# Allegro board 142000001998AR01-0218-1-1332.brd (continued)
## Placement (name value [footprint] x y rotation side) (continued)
R20  49.9  [RC0402]  90.95 114.25 90 top
R21  10K  [RC0402]  94.43 113.95 180 top
R22  @0  [RC0402]  69.56 113.52 90 top
R23  10K  [RC0402]  64.99 113.48 90 top
R24  10K  [RC0402]  77.82 113.39 270 top
R25  33  [RC0402]  86.72 113.31 90 top
R26  0  [RC0402]  90.95 113.28 90 top
R27  0  [RC0402]  73.56 112.88 90 top
R28  4.7K  [RC0402]  82.88 112.81 270 top
R29  @49.9  [RC0402]  69.57 112.6 270 top
R30  4.7K  [RC0402]  65 112.55 90 top
R31  0  [RC0402]  77.83 112.44 270 top
R32  0  [RC0402]  73.55 111.96 90 top
R33  10K  [RC0402]  60.2 111.82 90 top
R34  @10K  [RC0402]  131.17 112.17 90 top
R35  @0  [RC0402]  69.56 111.65 90 top
R36  @10K  [RC0402]  170.56 119.13 0 top
R37  0  [RC0402]  86.69 111.4 270 top
R38  @0  [RC0402]  81.46 110.97 0 top
R39  10K  [RC0402]  65 110.97 270 top
R40  0  [RC0402]  77.88 110.74 270 top
R41  33  [RC0402]  90.98 110.69 90 top
R42  3K  [RC0402]  132.18 111.05 270 top
R43  @4.7K  [RC0402]  82.88 110.54 270 top
R44  0  [RC0402]  73.58 110.49 90 top
R45  0  [RC0402]  86.69 110.44 270 top
R46  2K  [RC0402]  130.78 110.61 0 top
R47  0  [RC0402]  65 110.03 90 top
R48  0  [RC0402]  101.06 109.99 0 top
R49  @0  [RC0402]  100.08 109.99 0 top
R50  10K  [RC0402]  98.18 109.99 180 top
R51  49.9  [RC0402]  102.03 109.98 180 top
R52  33  [RC0402]  99.11 109.98 180 top
R53  10K  [RC0402]  97.2 109.96 0 top
R54  49.9  [RC0402]  96.24 109.96 180 top
R55  10K  [RC0402]  22.07 109.86 0 top
R56  @10K  [RC0402]  23.14 109.86 0 top
R57  4.7K  [RC0402]  77.87 109.81 270 top
R58  51  [RC0402]  20.98 109.8 0 top
R59  51  [RC0402]  17.75 109.78 0 top
R60  51  [RC0402]  19.46 109.78 0 top
R61  49.9  [RC0402]  69.54 109.78 270 top
R62  @10K  [RC0402]  169.54 119.13 180 top
R63  @4.7K  [RC0402]  86.66 109.5 90 top
R64  @10K  [RC0402]  94.08 109.37 270 top
R65  0  [RC0402]  90.5 109.25 0 top
R66  0  [RC0402]  64.99 109.07 90 top
R67  0  [RC0402]  77.88 108.84 90 top
R68  22.1K  [RC0402]  132.23 108.76 90 top
R69  0  [RC0402]  69.54 108.23 270 top
R70  33  [RC0402]  64.85 108.51 270 bottom
R71  1K  [RC0402]  93.59 108.05 0 top
R72  0  [RC0402]  94.59 108.05 180 top
R73  0  [RC0402]  73.73 108.05 270 top
R74  121K  [RC0402]  132.23 107.87 270 top
R75  0  [RC0402]  73.73 107.14 270 top
R77  0  [RC0402]  132.23 106.86 90 top
R78  33  [RC0402]  163.07 118.62 180 top
R79  0  [RC0402]  83.01 106.4 0 top
R80  0  [RC0402]  83.97 106.4 0 top
R82  0  [RC0402]  85.55 106.35 0 top
R83  0  [RC0402]  86.51 106.35 0 top
R84  10K  [RC0402]  78.69 106.02 180 top
R85  4.7K  [RC0402]  79.55 106.02 180 top
R86  0  [RC0402]  77.78 106.01 0 top
R87  0  [RC0402]  132.23 105.97 270 top
R88  0  [RC0402]  81.58 105.92 270 top
R89  @1K  [RC0402]  94.67 105.38 270 top
R90  4.7K  [RC0402]  89.64 105.52 180 top
R91  4.7K  [RC0402]  75.01 105.15 180 top
R92  0  [RC0402]  131.27 104.95 90 top
R93  0  [RC0402]  3.72 104.74 270 top
R94  10K  [RC0402]  71.15 104.57 180 top
R95  4.7K  [RC0402]  179.02 92.67 180 top
R96  @4.7K/DNI  [RC0402]  179.9 92.67 0 top
R97  4.7K  [RC0402]  180.92 92.67 0 top
R98  0  [RC0402]  72.54 104.17 180 top
R99  0/0603  [RC0603]  132.63 102.5 270 top
R100  10M  [RC0603]  95.5 103.76 90 top
R101  0  [RC0402]  74.55 103.73 90 top
R102  0  [RC0402]  85.45 103.73 0 top
R103  0  [RC0402]  86.41 103.73 0 top
R104  0  [RC0402]  87.5 103.73 0 top
R105  0  [RC0402]  79.55 103.68 180 top
R106  0  [RC0402]  83.87 103.68 180 top
R107  0  [RC0402]  77.65 103.59 0 top
R108  4.7K  [RC0402]  92.41 103.59 180 top
R109  4.7K  [RC0402]  93.32 103.59 180 top
R110  0  [RC0402]  91.49 103.58 180 top
R111  0  [RC0402]  88.65 103.55 0 top
R112  0  [RC0402]  89.64 103.55 0 top
R113  1K  [RC0603]  3.72 103.37 270 top
R114  @0  [RC0402]  82.3 103.22 0 top
R115  @0  [RC0402]  81.03 103.2 0 top
R116  0  [RC0402]  76.63 102.19 180 top
R117  20K  [RC0402]  99.26 102.08 180 top
R118  0  [RC0402]  100.23 102.08 0 top
R119  33  [RC0402]  160.02 114.17 0 bottom
R120  33  [RC0402]  159 114.17 0 bottom
R121  0  [RC0402]  88.55 100.55 0 top
R122  33  [RC0402]  103.99 100.39 0 top
R123  33  [RC0402]  104.98 100.39 0 top
R124  0  [RC0402]  90.17 100.22 0 top
R125  0  [RC0402]  91.57 100.18 0 top
R126  0  [RC0402]  92.91 100.13 0 top
R127  18K  [RC0603]  100.2 99.4 90 top
R128  33  [RC0402]  113.57 98.07 0 top
R129  33  [RC0402]  109.52 98.01 0 top
R130  33  [RC0402]  110.79 98.01 0 top
R131  0  [RC0402]  88.39 92.58 180 bottom
R132  0  [RC0402]  199.19 98.52 90 bottom
R133  0  [RC0402]  199.15 97.13 0 bottom
R134  0  [RC0402]  202.79 92.26 270 top
R135  0  [RC0402]  199.36 95.71 270 bottom
R136  33  [RC0402]  99.54 96.53 0 top
R137  0  [RC0402]  100.48 96.53 0 top
R138  0  [RC0402]  101.42 96.53 0 top
R139  0  [RC0402]  102.36 96.53 0 top
R140  1M  [RC0402]  98.61 96.52 180 top
R141  150  [RC0402]  105.61 95.56 0 top
R142  10K  [RC0402]  103.5 95.54 180 top
R143  10K  [RC0402]  104.47 95.54 180 top
R144  33  [RC0402]  106.76 95.51 0 top
R145  33  [RC0402]  107.72 95.51 0 top
R146  0  [RC0402]  96.65 97.41 180 top
R147  0  [RC0402]  202.23 93.32 270 bottom
R148  20ohm  [RC0402]  124.97 92.96 0 top
R149  0  [RC0402]  195.63 14.58 0 bottom
R150  0  [RC0402]  206.53 98.49 90 bottom
R151  0  [RC0402]  203.05 98.21 180 bottom
R152  4.7K  [RC0402]  186.07 44.76 90 bottom
R153  4.7K  [RC0402]  206.5 70.69 180 top
R154  1Kohm  [RC0402]  124.97 94.87 180 top
R155  @4.7K  [RC0402]  205.51 70.69 0 top
R156  @4.7K  [RC0402]  183.64 80.39 270 bottom
R157  @4.7K/DNI  [RC0402]  183.64 81.41 90 bottom
R158  @22  [RC0402]  187.58 80.77 180 bottom
R159  @22  [RC0402]  188.85 80.77 180 bottom
R163  220ohm  [RC0402]  165.99 81.03 180 top
R164  4.7K  [RC0402]  164.59 81.03 0 top
R169  10K  [RC0402]  169.77 84.95 90 top
R171  10K  [RC0402]  193.4 35.03 180 top
R172  33  [RC0402]  197.36 43.18 0 top
R173  10K  [RC0402]  169.71 83.04 90 top
R180  7.5K  [RC0402]  117.12 81.46 270 top
R182  0  [RC0402]  191.64 66.17 0 top
R184  0  [RC0402]  186.99 66.07 180 top
R185  0  [RC0402]  199.24 65.68 270 top
R186  0  [RC0402]  192.53 66.17 180 top
R187  10K  [RC0402]  201.04 66.04 0 top
R188  10K  [RC0402]  147.34 69.48 90 top
R189  0  [RC0402]  186.03 66.07 0 top
R192  0  [RC0603]  129.2 77.28 0 top
R193  4.12K  [RC0402]  130.36 76.74 0 top
R194  0  [RC0402]  202.31 66.04 0 top
R195  0  [RC0402]  203.58 66.04 0 top
R196  @5.11K  [RC0402]  117.16 70.34 270 top
R197  2.61K  [RC0603]  138.19 69.94 90 top
R198  0  [RC0603]  138.19 68.57 90 top
R199  @5.11K  [RC0402]  117.16 69.4 270 top
R200  1000  [RC0402]  67.64 70.48 0 top
R201  10K  [RC0402]  130.23 68.13 0 top
R202  5.11K  [RC0402]  116.64 67.97 180 top
R203  10K  [RC0402]  172.11 48.36 0 top
R204  49.9  [RC0402]  173.2 48.31 0 top
R205  0  [RC0603]  119.3 65.76 90 top
R206  49.9  [RC0402]  174.14 48.31 0 top
R207  1M  [RC0603]  119.28 64.19 270 top
R208  49.9  [RC0402]  175.08 48.31 0 top
R209  49.9  [RC0402]  176.02 48.31 0 top
R210  49.9  [RC0402]  176.96 48.31 0 top
R211  49.9  [RC0402]  68.27 61.49 270 top
R212  10K  [RC0402]  176.89 60.35 90 top
R213  5.1K  [RC0402]  118.59 61.34 90 top
R214  49.9  [RC0402]  177.9 48.31 0 top
R215  49.9  [RC0402]  68.27 60.55 270 top
R216  5.1K  [RC0402]  118.59 60.4 90 top
R217  10K  [RC0402]  118.59 59.46 90 top
R218  @10K  [RC0402]  190.75 66.17 0 top
R219  1000  [RC0402]  121.16 59.56 270 top
R220  10K  [RC0402]  118.59 58.52 90 top
R221  0  [RC0402]  184.66 47.5 270 top
R222  @4.7K  [RC0402]  118.59 57.58 270 top
R223  0  [RC0402]  207.11 43.76 0 top
R224  0  [RC0402]  199.14 43.43 270 top
R225  0  [RC0402]  191.03 43.59 90 top
R226  0  [RC0402]  189 43.56 270 top
R228  0  [RC0402]  192.79 43.1 180 top
R229  0  [RC0402]  200.66 43.18 0 top
R230  0  [RC0402]  194.28 65.96 0 bottom
R231  0  [RC0402]  201.83 43.18 0 top
R232  @4.7K  [RC0402]  118.59 56.64 90 top
R233  1K  [RC0402]  163.35 30.2 90 top
R234  4.7K  [RC0402]  121.87 55.16 180 top
R235  4.7K  [RC0402]  122.79 55.16 180 top
R236  33  [RC0402]  113.17 51.27 0 top
R237  10K  [RC0402]  98.8 51.21 0 top
R238  0  [RC0402]  99.98 51.21 0 top
R239  0  [RC0402]  101.06 51.18 0 top
R240  0  [RC0402]  110.18 51.18 0 top
R241  0  [RC0402]  103.2 51.18 180 top
R242  0  [RC0402]  108.79 51.16 0 top
R243  0  [RC0402]  107.49 51.16 180 top
R244  10K  [RC0402]  114.22 51.15 0 top
R245  @5.1k/1%  [RC0402]  103.61 48.04 0 top
R246  0  [RC0402]  106.32 51.13 180 top
R247  0  [RC0402]  104.37 51.13 180 top
R248  0  [RC0402]  105.46 51.13 0 top
R249  10K  [RC0402]  171.91 23.04 180 bottom
R250  10K  [RC0402]  98.8 48.46 180 top
R251  10K  [RC0402]  104.47 48.04 0 top
R252  0  [RC0402]  106.1 48.03 0 top
R253  0  [RC0402]  106.96 48.03 0 top
R254  0  [RC0402]  102.21 48.03 180 top
R255  0  [RC0402]  107.98 48.03 0 top
R256  0  [RC0402]  101.06 48.01 0 top
R257  0  [RC0402]  99.98 48 180 top
R258  5.11K  [RC0402]  97.03 47.24 90 top
R259  @5.11K  [RC0402]  97.03 48.26 90 top
R260  49.9  [RC0402]  105.46 45.67 180 top
R261  @49.9  [RC0402]  98.55 45.09 180 top
R262  1000  [RC0402]  99.57 44.96 180 top
R263  @10K  [RC0402]  101.06 44.91 0 top
R264  @10K  [RC0402]  102.21 44.91 0 top
R265  0  [RC0402]  103.31 44.91 0 top
R266  5.11K  [RC0402]  104.37 44.91 0 top
R267  1K  [RC0402]  106.45 44.91 0 top
R268  @4.7K  [RC0402]  107.62 44.91 0 top
R269  10K  [RC0402]  108.79 44.91 180 top
R270  10K  [RC0402]  110.18 44.91 180 top
R271  @4.7K  [RC0402]  111.15 44.91 180 top
R272  4.7K  [RC0402]  112.12 44.91 0 top
R273  33  [RC0402]  113.08 44.91 0 top
R274  4.7K  [RC0402]  114.25 44.91 0 top
R275  4.7K  [RC0402]  97.49 44.6 180 top
R276  @49.9  [RC0402]  96.57 44.6 180 top
R277  0  [RC0402]  174.52 30.38 270 top
R278  0  [RC0402]  174.52 31.32 90 top
R279  71.5K  [RC0603]  174.75 32.54 270 top
R280  0  [RC0402]  174.32 33.81 90 top
R281  2K  [RC0402]  174.32 35.59 90 top
R282  3K  [RC0402]  174.32 36.47 270 top
R283  0  [RC0402]  108.76 38.51 0 top
R284  @4.7K  [RC0402]  97.49 42.01 180 top
R285  10K  [RC0402]  96.57 42.01 180 top
R286  200  [RC0402]  98.8 41.99 180 top
R287  0  [RC0402]  109.7 38.51 0 top
R288  0  [RC0402]  99.98 41.78 180 top
R289  5.11K  [RC0402]  101.06 41.78 0 top
R290  @4.7K  [RC0402]  104.37 41.78 0 top
R291  @10K  [RC0402]  105.46 41.78 0 top
R292  @4.7K  [RC0402]  106.45 41.78 0 top
R293  10K  [RC0402]  107.62 41.78 0 top
R294  10K  [RC0402]  108.79 41.78 0 top
R295  10K  [RC0402]  110.18 41.78 0 top
R296  4.7K  [RC0402]  111.15 41.78 0 top
R297  @75  [RC0402]  136.78 111.63 90 top
R298  4.7K  [RC0402]  136.78 109.22 270 top
R299  0  [RC0402]  136.78 110.36 270 top
R300  4.7K  [RC0402]  111.1 38.02 90 top
R301  33  [RC0402]  111.1 38.99 270 top
R302  33  [RC0402]  112.55 38.51 180 top
R303  33  [RC0402]  101.09 39.07 90 top
R304  0  [RC0402]  98.8 38.86 180 top
R305  @49.9  [RC0402]  96.57 38.71 180 top
R306  4.7K  [RC0402]  97.94 37.29 0 top
R307  75  [RC0402]  100.97 36.83 0 top
R308  240/5%  [RC0402]  96.72 35.13 180 top
R309  4.7K  [RC0402]  97.94 34.79 180 top
R310  0/0603  [RC0603]  152.45 69.22 270 top
R311  4.7K  [RC0402]  147.19 108.71 90 top
R312  4.7K  [RC0402]  147.19 109.86 90 top
R313  4.7K  [RC0402]  147.19 112.27 90 top
R314  @4.7K  [RC0402]  147.19 111.25 270 top
R315  33  [RC0402]  9.71 30.93 90 top
R316  0  [RC0402]  153.09 70.61 270 top
R317  @10K  [RC0402]  15.64 30.59 90 top
R318  10K  [RC0402]  18.16 30.59 90 top
R319  1K  [RC0402]  43.08 30.16 270 top
R320  10K@25C THERMISTOR  [RC0402]  64.11 30.02 180 top
R321  33  [RC0402]  9.71 29.66 90 top
R322  10K  [RC0402]  15.64 29.57 90 top
R323  @10K  [RC0402]  18.16 29.57 90 top
R324  27K  [RC0603]  152.45 72.64 0 top
R325  0  [RC0402]  43.08 29.21 270 top
R326  47K/1%  [RC0402]  55.07 28.73 0 top
R327  0  [RC0402]  9.71 28.39 270 top
R328  0  [RC0603]  154.61 74.3 270 top
R329  0  [RC0402]  9.71 27.12 90 top
R330  10  [RC0402]  156.64 74.68 0 top
R331  0  [RC0402]  9.71 25.85 90 top
R332  0  [RC0402]  9.71 24.58 90 top
R333  0  [RC0402]  60.86 24.53 90 top
R334  1000  [RC0402]  35.84 24.09 90 top
R335  0  [RC0402]  60.86 23.59 90 top
R336  0  [RC0402]  9.71 23.31 90 top
R337  3K  [RC0402]  35.84 23.14 270 top
R338  0  [RC0402]  9.71 22.04 90 top
R339  0  [RC0402]  35.84 21.28 90 top
R340  0.003  [RC2512]  162.43 20.95 90 top
R341  0  [RC0402]  9.71 20.77 90 top
R342  0  [RC0805]  79.7 20.36 0 top
R343  0  [RC0805]  60.91 19.81 0 top
R344  22.1K  [RC0402]  36.37 19.76 0 top
R345  10  [RC0402]  35.89 18.39 270 top
R346  @0  [RC0402]  11.48 16.56 180 top
R347  4.7K  [RC0402]  56.11 16.49 90 top
R348  1.74K  [RC0402]  61.07 14.7 270 top
R349  @100  [RC0402]  58.06 14.43 180 top
R350  @100  [RC0402]  59 14.43 0 top
R351  4.02K  [RC0402]  72.78 14 90 top
R352  1K  [RC0402]  77.41 13.99 270 top
R353  1K  [RC0402]  74.64 13.96 270 top
R354  4.02K  [RC0402]  78.83 13.5 0 top
R355  4.02K  [RC0402]  76.04 13.48 0 top
R356  1.05K  [RC0603]  60.3 12.76 180 top
R357  1.05K  [RC0603]  61.7 12.76 180 top
R358  0  [RC0402]  58.06 12.09 180 top
R359  0  [RC0402]  59 12.09 180 top
R360  12K  [RC0402]  81.79 12.19 90 top
R361  12K  [RC0402]  69.98 11.56 180 top
R362  13K  [RC0402]  53.26 10.64 90 top
R363  1000  [RC0402]  53.26 9.68 270 top
R364  0  [RC0402]  69.04 9.66 270 top
R365  22  [RC0402]  65.43 8.75 270 top
R366  0  [RC0402]  69.04 8.73 270 top
R367  1000  [RC0402]  96.4 8.71 90 top
R368  301  [RC0402]  62.71 8.45 90 top
R369  @0  [RC0402]  50.12 8.23 90 top
R370  0  [RC0402]  52.75 7.85 270 top
R371  6.49K  [RC0402]  70.11 7.82 270 top
R372  976  [RC0603]  65.12 7.58 90 top
R373  301  [RC0402]  62.71 7.48 90 top
R374  40.2  [RC0402]  50.12 7.29 270 top
R375  0  [RC0805]  80.19 7.11 180 top
R376  200  [RC0402]  52.5 6.91 270 top
R377  10K  [RC0402]  70.11 6.87 90 top
R378  33  [RC0402]  9.71 33.47 270 top
R379  121  [RC0402]  50.12 6.35 270 top
R380  0  [RC0402]  152.35 33.25 0 top
R381  2K  [RC0402]  154.18 33.25 0 top
R382  3K  [RC0402]  155.12 33.25 180 top
R383  0  [RC0402]  149.53 33.21 180 top
R384  73.2K  [RC0402]  150.44 33.2 180 top
R385  5.1  [RC0402]  52.6 6.03 270 top
R386  1000  [RC0402]  102.04 5.24 180 top
R387  0  [RC0402]  70.08 4.88 270 top
R388  0  [RC0402]  150.01 31.8 90 top
R389  10  [RC0402]  188.34 8.89 0 top
R390  10K  [RC0402]  190.37 8.89 180 top
R391  0  [RC0805]  62.91 4.41 0 top
R392  0  [RC0402]  52.32 4.19 270 top
R393  0  [RC0402]  70.08 3.99 270 top
R394  0  [RC0402]  75.41 3.96 0 top
R395  0  [RC0402]  76.33 3.96 0 top
R396  0  [RC0402]  78.46 3.94 0 top
R397  0  [RC0402]  79.4 3.94 0 top
R398  0  [RC0402]  53.72 4.06 0 top
R399  200  [RC0402]  73.51 3.44 180 top
R400  5.1  [RC0402]  74.44 3.44 0 top
R401  0  [RC0402]  72.59 3.42 0 top
R402  845  [RC0402]  70.08 3.1 270 top
R403  0  [RC0402]  50.67 2.54 0 top
R404  150  [RC0402]  191.24 119.54 0 bottom
R405  100  [RC0402]  192.28 119.54 0 bottom
R406  100  [RC0402]  193.28 119.54 0 bottom
R407  100  [RC0402]  197.87 119.54 0 bottom
R408  100  [RC0402]  199.02 119.54 0 bottom
R409  100  [RC0402]  200.67 119.54 0 bottom
R410  100  [RC0402]  202.06 119.54 0 bottom
R411  100  [RC0402]  203.46 119.54 0 bottom
R412  100  [RC0402]  205.11 119.54 0 bottom
R413  100  [RC0402]  206.51 119.54 0 bottom
R414  10K  [RC0402]  28.48 119.74 0 bottom
R415  10K  [RC0402]  29.39 119.74 0 bottom
R416  10K  [RC0402]  30.33 119.74 0 bottom
R417  51  [RC0402]  18.71 119.74 0 bottom
R418  10K  [RC0402]  24.41 119.74 0 bottom
R419  10K  [RC0402]  25.33 119.74 0 bottom
R420  10K  [RC0402]  26.27 119.74 0 bottom
R421  10K  [RC0402]  27.21 119.74 0 bottom
R422  10K  [RC0402]  21.52 119.74 0 bottom
R423  0  [RC0402]  22.48 119.74 180 bottom
R424  1K  [RC0402]  23.42 119.74 0 bottom
R425  0  [RC0402]  19.66 119.73 180 bottom
R426  0  [RC0402]  20.57 119.73 180 bottom
R427  10K  [RC0402]  112.9 115.44 90 bottom
R429  10K  [RC0402]  61.32 115.86 90 bottom
R430  4.7K  [RC0402]  73.58 115.39 270 bottom
R431  10K  [RC0402]  82.85 115.34 270 bottom
R432  4.7K  [RC0402]  86.74 115.26 270 bottom
R433  4.7K  [RC0402]  31.12 115.09 270 bottom
R435  10K  [RC0402]  114.81 115.95 0 bottom
R436  1K  [RC0402]  28.63 114.61 180 bottom
R437  10K  [RC0402]  29.54 114.61 180 bottom
R438  10K  [RC0402]  82.85 114.38 270 bottom
R439  0  [RC0402]  90.95 114.25 270 bottom
R440  10K  [RC0402]  94.43 113.95 0 bottom
R441  0  [RC0402]  30.53 113.74 180 bottom
R442  4.7K  [RC0402]  31.7 113.74 0 bottom
R443  4.7K  [RC0402]  86.72 113.31 270 bottom
R444  0  [RC0402]  73.56 112.88 270 bottom
R445  @4.7K  [RC0402]  65 112.55 90 bottom
R446  4.7K  [RC0402]  77.83 112.44 270 bottom
R447  10K  [RC0402]  60.2 111.82 270 bottom
R448  4.7K  [RC0402]  90.98 111.66 270 bottom
R449  10K  [RC0402]  86.69 111.4 90 bottom
R450  0  [RC0402]  81.46 110.97 180 bottom
R451  0  [RC0402]  65 110.97 90 bottom
R452  4.7K  [RC0402]  90.98 110.69 270 bottom
R453  @49.9  [RC0402]  72.09 110.54 0 bottom
R454  10K  [RC0402]  82.88 110.54 270 bottom
R455  30K  [RC0402]  128.5 110.44 0 bottom
R456  2K  [RC0402]  97.69 110.41 270 bottom
R457  2K  [RC0402]  102.03 109.98 180 bottom
R458  4.7K  [RC0402]  86.66 109.5 90 bottom
R459  10K  [RC0402]  75.41 109.25 90 bottom
R460  10K  [RC0402]  59.66 109.22 0 bottom
R461  2K  [RC0402]  68.76 109.12 270 bottom
R462  33  [RC0402]  81.05 108.8 90 bottom
R463  1000  [RC0402]  69.54 108.23 90 bottom
R464  0  [RC0402]  93.59 108.05 0 bottom
R465  10K  [RC0402]  157.53 119.58 180 bottom
R466  4.7K  [RC0402]  73.28 107.59 0 bottom
R467  4.7K  [RC0402]  83.52 106.85 90 bottom
R468  @10K  [RC0402]  158.78 119.6 0 bottom
R469  0  [RC0402]  77.7 106.01 180 bottom
R470  @4.7K  [RC0402]  86.06 105.95 90 bottom
R471  @0  [RC0402]  83.52 105.94 270 bottom
R473  4.7K  [RC0402]  76.73 105.23 0 bottom
R474  0  [RC0402]  74.55 103.73 270 bottom
R475  0  [RC0402]  87.5 103.73 180 bottom
R476  0  [RC0402]  79.55 103.68 180 bottom
R477  0  [RC0402]  77.65 103.59 180 bottom
R478  4.7K  [RC0402]  92.84 103.56 0 bottom
R479  0  [RC0402]  88.65 103.55 180 bottom
R480  0  [RC0402]  89.64 103.55 180 bottom
R481  @4.7K  [RC0402]  85.96 103.28 90 bottom
R482  0  [RC0402]  81.03 103.2 180 bottom
R483  10K  [RC0402]  94.61 93.47 90 bottom
R485  10K  [RC0402]  94.61 94.36 90 bottom
R486  0  [RC0402]  103.99 100.65 0 bottom
R487  7.5K  [RC0402]  106.32 100.64 180 bottom
R488  0  [RC0402]  82.8 117.73 270 bottom
R489  0  [RC0402]  88.55 100.55 180 bottom
R490  0  [RC0402]  90.17 100.22 180 bottom
R491  4.7K  [RC0402]  22.54 99.64 0 bottom
R492  @4.7K  [RC0402]  23.47 99.64 180 bottom
R493  33  [RC0402]  19.96 99.6 0 bottom
R494  4.7K  [RC0402]  20.9 99.6 0 bottom
R495  4.7K  [RC0402]  18.11 99.59 180 bottom
R496  4.7K  [RC0402]  19.03 99.59 180 bottom
R497  33  [RC0402]  25.11 99.57 180 bottom
R498  33  [RC0402]  27.56 99.54 180 bottom
R499  365K  [RC0603]  100.2 99.14 90 bottom
R500  0  [RC0402]  82.07 102.03 0 bottom
R501  10K  [RC0402]  101.06 109.99 180 bottom
R502  @4.7K  [RC0402]  107.57 39.62 270 bottom
R503  10K  [RC0402]  202.82 43.18 180 top
R504  10K  [RC0402]  6.99 27.12 270 top
R505  330K  [RC0402]  98.35 96.52 0 bottom
R506  0  [RC0402]  99.29 96.52 180 bottom
R507  49.9  [RC0402]  105.61 95.43 180 bottom
R508  0ohm  [RC0402]  116.78 94.93 90 bottom
R509  0ohm  [RC0402]  116.78 93.61 90 bottom
R510  10K  [RC0402]  6.99 25.85 270 top
R511  10K  [RC0402]  6.99 24.58 270 top
R512  10K  [RC0402]  6.99 20.77 270 top
R513  10K  [RC0402]  6.99 23.31 270 top
R514  10K  [RC0402]  6.99 22.04 270 top
R515  22.6  [RC0402]  100.46 90.4 0 bottom
R516  @10K  [RC0402]  82.4 100.63 90 bottom
R517  @0  [RC0402]  85.83 90.8 180 bottom
R518  @10K  [RC0402]  94.74 96.27 270 bottom
R519  10K  [RC0402]  103.25 90.42 0 bottom
R520  4.7K  [RC0402]  95.83 91.19 0 bottom
R521  @10K  [RC0402]  82.88 112.81 90 bottom
R522  33  [RC0402]  104.27 89.41 180 bottom
R523  @10K  [RC0402]  96.77 91.19 180 bottom
R524  @1K  [RC0402]  99.95 36.83 180 top
R525  4.7K  [RC0402]  24.85 87.61 180 bottom
R526  @4.7K  [RC0402]  25.76 87.61 0 bottom
R527  @4.7K  [RC0402]  26.72 87.61 0 bottom
R528  4.7K  [RC0402]  27.59 87.61 180 bottom
R529  33  [RC0402]  19.36 87.58 180 bottom
R530  4.7K  [RC0402]  20.3 87.58 180 bottom
R531  33  [RC0402]  21.21 87.58 180 bottom
R532  4.7K  [RC0402]  22.13 87.58 180 bottom
R533  4.7K  [RC0402]  23.04 87.58 180 bottom
R534  33  [RC0402]  23.93 87.58 180 bottom
R535  8.2K  [RC0603]  107.26 87.96 180 bottom
R536  33  [RC0402]  169.77 84.95 270 bottom
R537  @33  [RC0402]  169.15 83.49 0 bottom
R538  33  [RC0402]  170.17 83.49 180 bottom
R539  33  [RC0402]  9.71 32.2 270 top
R540  @0  [RC0402]  24.97 84.2 90 bottom
R541  10K  [RC0402]  169.78 82.02 90 bottom
R542  10K  [RC0402]  169.78 80.96 90 bottom
R543  7.5K  [RC0402]  106.93 80.8 90 bottom
R544  10K  [RC0402]  106.81 77.55 0 bottom
R545  10K  [RC0402]  107.75 77.55 0 bottom
R546  0  [RC0402]  56.34 77.42 0 bottom
R547  10K  [RC0402]  93.4 76.91 180 bottom
R548  10K  [RC0402]  103.99 76.71 180 bottom
R549  10K  [RC0402]  102.97 76.68 180 bottom
R550  1000  [RC0402]  144.74 70.08 0 bottom
R551  0  [RC0402]  44.01 76.53 0 bottom
R552  33  [RC0402]  176.94 74.83 270 top
R553  10K  [RC0402]  91.11 75.46 180 bottom
R554  1K  [RC0402]  85.75 74.52 180 bottom
R555  4.12K  [RC0402]  142.42 69.8 90 bottom
R556  10K  [RC0402]  173.13 72.82 0 bottom
R557  100  [RC0402]  79.6 73.13 270 bottom
R558  4.7K  [RC0402]  130.43 73.13 0 bottom
R559  100  [RC0402]  79.38 71.71 270 bottom
R560  0  [RC0402]  88.57 71.53 270 bottom
R561  1000  [RC0402]  133.15 71.4 270 bottom
R562  0  [RC0402]  72.01 71.07 90 bottom
R563  10K  [RC0402]  172.54 69.34 90 bottom
R564  121  [RC0402]  88.24 70.17 270 bottom
R565  40.2  [RC0402]  88.24 69.27 270 bottom
R566  100  [RC0402]  76.76 67.59 270 bottom
R567  200  [RC0402]  170.59 54.05 0 bottom
R568  130  [RC0402]  88.24 68.35 270 bottom
R569  1K(1%)  [RC0402]  108.74 68.28 180 bottom
R570  0  [RC0402]  41.74 67.81 180 bottom
R571  100  [RC0402]  74.78 67.59 270 bottom
R572  49.9  [RC0402]  177.09 66.27 180 bottom
R573  10K  [RC0402]  173.13 65.48 0 bottom
R574  0  [RC0402]  54.84 66.37 90 bottom
R575  10K  [RC0402]  173.18 54.03 0 bottom
R576  33  [RC0402]  25.7 63.65 270 bottom
R577  10K  [RC0402]  172.24 62.03 90 bottom
R578  4.7K  [RC0402]  99.59 62.48 270 bottom
R579  33  [RC0402]  25.7 62.38 270 bottom
R580  1000  [RC0402]  53.58 61.19 90 bottom
R581  33  [RC0402]  25.68 61.36 270 bottom
R582  @4.7K  [RC0402]  111.3 61.01 180 bottom
R583  @240  [RC0402]  118.08 60.4 90 bottom
R584  4.7K  [RC0402]  105.79 60.3 180 bottom
R585  33  [RC0402]  25.68 60.37 270 bottom
R586  4.7K  [RC0402]  111.71 59.59 270 bottom
R587  @49.9  [RC0402]  118.08 59.46 90 bottom
R589  33  [RC0402]  118.08 58.52 90 bottom
R590  @4.7K  [RC0402]  118.08 57.58 270 bottom
R592  0  [RC0402]  57.45 57.27 180 bottom
R593  0  [RC0402]  58.38 57.27 180 bottom
R594  100  [RC0402]  103.33 57.02 0 bottom
R595  10K  [RC0402]  104.27 57.02 0 bottom
R596  10K  [RC0402]  105.21 57.02 0 bottom
R597  4.7K  [RC0402]  118.08 56.64 270 bottom
R598  4.7K  [RC0402]  112.83 56.57 180 bottom
R599  @100  [RC0402]  97.71 55.42 270 bottom
R600  @100  [RC0402]  97.71 54.48 90 bottom
R601  4.7K  [RC0402]  117.22 54.15 180 bottom
R602  @4.7K  [RC0402]  118.11 54.15 180 bottom
R603  4.7K  [RC0402]  30.48 50.16 180 bottom
R604  @100  [RC0402]  97.76 53.29 270 bottom
R605  @100  [RC0402]  97.76 52.38 90 bottom
R606  2.2K  [RC0402]  25.38 51.63 0 bottom
R607  4.7K  [RC0402]  30.48 52.2 0 bottom
R608  10K  [RC0402]  167.08 38.76 270 bottom
R609  1K  [RC0402]  99.98 51.21 0 bottom
R610  @49.9  [RC0402]  101.06 51.18 180 bottom
R611  12.7K  [RC0402]  168.99 38.76 270 bottom
R612  10K  [RC0402]  170.42 39.21 180 bottom
R613  0  [RC0402]  104.27 48.36 270 bottom
R614  1000  [RC0402]  101.06 48.01 180 bottom
R615  10K  [RC0402]  104.27 47.5 90 bottom
R616  @10K  [RC0402]  96.57 47.75 180 bottom
R617  4.7K  [RC0402]  113.41 47.12 270 bottom
R618  10K  [RC0402]  117.55 46.73 180 bottom
R619  33  [RC0402]  116.38 46.69 180 bottom
R620  0/0603  [RC0603]  172.21 38.61 180 top
R621  0  [RC0402]  91.97 46.1 180 bottom
R622  0  [RC0402]  92.91 46.1 180 bottom
R623  10K  [RC0402]  95.15 45.49 180 bottom
R624  240/5%  [RC0402]  98.02 45.06 90 bottom
R625  5.11K  [RC0402]  102.21 44.91 0 bottom
R626  @10K  [RC0402]  104.37 44.91 0 bottom
R627  4.7K  [RC0402]  114.25 44.91 180 bottom
R628  10K  [RC0402]  116.76 44.48 90 bottom
R629  22.1K  [RC0402]  173.81 33.93 0 bottom
R630  @4.7K  [RC0402]  112.57 44.58 90 bottom
R631  10K  [RC0402]  171.7 19.05 180 bottom
R632  @4.7K  [RC0402]  105.64 43.71 90 bottom
R633  4.7K  [RC0402]  95.15 42.32 90 bottom
R634  0  [RC0402]  102.69 42.27 270 bottom
R635  @240/5%  [RC0402]  100.61 42.21 270 bottom
R636  121  [RC0402]  98.8 41.99 180 bottom
R637  @4.7K  [RC0402]  111.15 41.78 180 bottom
R638  4.7K  [RC0402]  95.15 41.25 90 bottom
R639  @49.9  [RC0402]  102.86 40.16 90 bottom
R640  33  [RC0402]  115.87 39.42 90 bottom
R641  0  [RC0402]  198.5 14.66 0 bottom
R642  49.9  [RC0402]  101.09 39.07 270 bottom
R643  49.9  [RC0402]  98.8 38.86 180 bottom
R644  @4.7Kohm  [RC0402]  188.01 23.27 270 bottom
R645  240  [RC0402]  96.57 38.71 180 bottom
R646  0  [RC0402]  33.19 38.53 90 bottom
R647  0  [RC0402]  36.41 38.18 270 bottom
R648  0  [RC0402]  38.21 38.18 90 bottom
R649  0  [RC0402]  50.57 38.13 90 bottom
R650  33  [RC0402]  197.99 19.48 0 bottom
R651  4.7K  [RC0402]  188.01 22.38 90 bottom
R652  @0  [RC0402]  33.19 37.61 90 bottom
R653  33  [RC0402]  199.01 19.48 0 bottom
R654  0  [RC0402]  44.78 37.14 0 bottom
R655  @0  [RC0402]  45.69 37.14 0 bottom
R656  0  [RC0402]  48.26 37.12 90 bottom
R657  4.7K  [RC0402]  92.27 37.06 0 bottom
R658  4.7K  [RC0402]  93.16 37.06 0 bottom
R659  @4.7K  [RC0402]  94.05 37.06 0 bottom
R660  4.7K  [RC0402]  188.01 21.41 90 bottom
R661  4.7K  [RC0402]  203.07 19.48 180 bottom
R662  33  [RC0402]  177.19 58.91 0 top
R663  @4.7K  [RC0402]  182.8 20.9 270 bottom
R664  0  [RC0402]  195.66 19.66 0 bottom
R665  @10K  [RC0402]  196.67 19.66 180 bottom
R666  @33  [RC0402]  200.03 19.48 0 bottom
R667  169  [RC0603]  99.97 36.17 180 bottom
R668  33  [RC0402]  204.09 19.48 180 bottom
R669  @33  [RC0402]  205.1 19.48 0 bottom
R670  33  [RC0402]  206.12 19.48 0 bottom
R671  33  [RC0402]  207.14 19.48 0 bottom
R672  @4.7Kohm  [RC0402]  188.01 20.52 270 bottom
R673  4.7K  [RC0402]  182.8 19.99 90 bottom
R674  33  [RC0402]  201.04 19.48 180 bottom
R675  0  [RC0402]  93.19 35.21 180 bottom
R676  @0  [RC0402]  94.1 35.21 180 bottom
R677  @4.7K  [RC0402]  188.01 19.58 270 bottom
R678  @4.7K  [RC0402]  50.97 34.65 180 bottom
R679  4.7K  [RC0402]  51.92 34.65 180 bottom
R680  @4.7K  [RC0402]  53.92 39.09 180 bottom
R681  4.7K  [RC0402]  54.18 34.65 180 bottom
R682  4.7K  [RC0402]  38.83 34.6 180 bottom
R683  @4.7K  [RC0402]  39.78 34.6 180 bottom
R684  @4.7K  [RC0402]  40.79 34.6 180 bottom
R685  4.7K  [RC0402]  41.73 34.6 180 bottom
R686  4.7K  [RC0402]  202.06 19.48 180 bottom
R687  4.7Kohm  [RC0402]  188.01 18.62 90 bottom
R688  4.7K  [RC0402]  43.12 34.06 180 bottom
R689  @4.7K  [RC0402]  44.07 34.06 180 bottom
R690  4.7K  [RC0402]  34.9 33.99 180 bottom
R691  @4.7K  [RC0402]  35.84 33.99 180 bottom
R692  1000  [RC0402]  152.96 67.82 270 top
R693  49.9/0603  [RC0603]  56.48 31.73 270 bottom
R694  3K  [RC0402]  157.06 69.6 90 bottom
R695  0  [RC0402]  193.71 19.68 0 bottom
R696  0  [RC0402]  193.65 14.5 180 bottom
R697  2K  [RC0402]  155.69 70.06 0 bottom
R698  22.1K  [RC0402]  150.8 71.63 270 top
R699  10K  [RC0402]  38.5 29.01 180 bottom
R700  10K  [RC0402]  38.05 27.59 90 bottom
R701  2K  [RC0402]  33.32 22.93 180 bottom
R702  33  [RC0402]  194.31 4.22 0 bottom
R703  1000  [RC0402]  195.25 4.22 0 bottom
R704  33  [RC0402]  197.59 4.22 0 bottom
R705  10K  [RC0402]  198.48 4.14 180 bottom
R706  33  [RC0402]  199.42 4.14 0 bottom
R707  10K  [RC0402]  203.78 3.35 270 bottom
R708  49.9K  [RC0603]  36.17 20.42 90 bottom
R709  0/0603  [RC0603]  30.56 19.94 270 bottom
R710  1/1%/0603  [RC0603]  53.98 19.33 180 bottom
R711  0  [RC0603]  36.17 19.08 270 bottom
R712  10K  [RC0402]  186.69 8.89 180 top
R713  @10  [RC0402]  185.17 10.41 270 top
R714  10  [RC0402]  184.66 8.89 0 top
R715  0  [RC0805]  123.9 14.71 90 bottom
R716  200  [RC0402]  187.04 14.88 180 bottom
R717  220ohm  [RC0402]  188.82 14.28 0 bottom
R718  220ohm  [RC0402]  190.6 14.28 0 bottom
R719  13K  [RC0402]  84.91 14.58 0 bottom
R720  1K  [RC0402]  85.85 14.58 0 bottom
R721  220ohm  [RC0402]  182.93 13.83 270 bottom
R722  220ohm  [RC0402]  184.81 13.83 90 bottom
R723  0  [RC0402]  56.69 13.77 90 bottom
R724  1K  [RC0402]  72.78 13.03 90 bottom
R725  0  [RC0402]  35.39 12.52 180 bottom
R726  51  [RC0402]  39.8 12.29 270 bottom
R727  0/0603  [RC0603]  154.48 39.29 90 bottom
R728  13K  [RC0402]  57.18 11.71 0 bottom
R729  75  [RC0402]  55.73 10.7 90 bottom
R730  976  [RC0603]  40.34 9.73 0 bottom
R731  1000  [RC0402]  155.13 36.63 180 bottom
R732  0  [RC0402]  154.23 36.63 180 bottom
R733  0  [RC0402]  80.19 9.53 90 bottom
R734  4.7K  [RC0402]  68.66 9.46 0 bottom
R735  @4.7K  [RC0402]  69.6 9.46 0 bottom
R736  1K  [RC0402]  36.37 9.19 180 bottom
R737  51  [RC0402]  37.3 9.19 0 bottom
R738  51  [RC0402]  38.24 9.19 0 bottom
R739  51  [RC0402]  39.17 9.19 0 bottom
R740  4.7K  [RC0402]  72.92 8.94 270 bottom
R741  0  [RC0402]  80.19 8.63 90 bottom
R742  1.78K/1%  [RC0603]  52.58 8.89 90 bottom
R743  7.5K  [RC0402]  57.56 8.26 90 bottom
R744  4.7K  [RC0402]  72.92 8 270 bottom
R745  0  [RC0402]  119.61 4.63 180 bottom
R746  4.7K  [RC0402]  79.56 6.94 0 bottom
R747  @4.7K  [RC0402]  80.5 6.94 0 bottom
R748  22.1K  [RC0402]  149.99 33.67 90 bottom
R749  @4.7K  [RC0402]  110.18 51.18 0 bottom
R750  4.7K  [RC0402]  76.02 6.1 0 bottom
R751  0  [RC0402]  117.07 5.54 180 bottom
R752  100K  [RC0402]  101.07 5.24 180 bottom
R753  @4.7K  [RC0402]  116.61 6.91 90 bottom
R754  1K  [RC0402]  33.38 4.67 90 bottom
R755  1000  [RC0402]  54.41 4.45 180 bottom
R756  1.78K  [RC0603]  52.43 4.39 90 bottom
R757  845  [RC0402]  77.25 3.96 180 bottom
R758  4.7K  [RC0402]  58.58 3.76 270 bottom
R759  0  [RC0402]  34.8 3.43 0 bottom
R760  150  [RC0402]  35.71 3.43 0 bottom
R761  3.3K  [RC0402]  36.63 3.43 0 bottom
R762  0  [RC0402]  37.54 3.43 0 bottom
R763  0  [RC0402]  38.46 3.43 0 bottom
R764  51  [RC0402]  39.39 3.43 0 bottom
R765  0  [RC0402]  40.34 3.43 0 bottom
R766  10K  [RC0402]  28.07 3.4 0 bottom
R767  10K  [RC0402]  28.96 3.4 0 bottom
R768  51  [RC0402]  30.51 3.4 0 bottom
R769  51  [RC0402]  31.45 3.4 0 bottom
R770  0  [RC0402]  49.66 2.54 0 top
R771  51  [RC0402]  24.12 3.39 0 bottom
R772  10K  [RC0402]  25.06 3.39 0 bottom
R773  51  [RC0402]  26 3.39 0 bottom
R774  51  [RC0402]  26.91 3.39 0 bottom
R775  @0  [RC0402]  32.89 3.3 180 bottom
R776  @0  [RC0402]  33.81 3.3 180 bottom
R777  0  [RC0402]  79.76 3.17 90 bottom
R778  100K  [RC0402]  97.15 3.17 0 bottom
R779  100K  [RC0402]  98.1 3.17 0 bottom
R780  0/0603  [RC0603]  56.13 14.99 90 bottom
R783  @4.7K  [RC0402]  114.53 6.46 0 bottom
R784  0  [RC0402]  114.53 4.63 180 bottom
R785  100  [RC0402]  105.97 58.55 270 bottom
R786  @33  [RC0402]  16.24 87.74 270 bottom
R787  4.7K  [RC0402]  103.25 51.18 0 bottom
R788  @33  [RC0402]  16.24 86.85 270 bottom
R789  33  [RC0402]  90.98 111.66 270 top
R790  0  [RC0402]  90.5 109.25 0 bottom
R791  @0  [RC0402]  16.24 89.61 270 bottom
R792  @0  [RC0402]  16.24 88.68 270 bottom
R793  @4.7K  [RC0402]  101.98 51.18 180 top
R794  5.1K  [RC0402]  116.71 51.18 180 top
R795  @1K  [RC0402]  110.87 54.48 0 bottom
R796  @10K  [RC0402]  103 38.1 270 top
R797  5.1K  [RC0402]  103 37.08 90 top
R798  @10K  [RC0402]  103 39.12 270 top
R799  5.1K  [RC0402]  103 40.13 90 top
R800  1K  [RC0402]  135.89 117.6 0 bottom
R801  100K  [RC0402]  165.1 108.46 180 top
R802  10K  [RC0402]  169.29 105.03 180 top
R803  0ohm  [RC0402]  166.88 111.63 270 bottom
R806  0  [RC0603]  142.75 79.63 180 top
R807  10K  [RC0402]  136.78 78.49 180 top
R808  10K  [RC0402]  140.21 78.49 180 top
R809  33  [RC0402]  138.3 97.03 180 top
R811  33  [RC0402]  135.25 97.03 180 top
R812  33  [RC0402]  137.29 97.03 180 top
R813  @10K  [RC0402]  135.64 106.3 270 top
R814  10K  [RC0402]  148.34 104.14 90 top
R815  10K  [RC0402]  135.64 105.28 270 top
R816  10K  [RC0402]  148.34 102.87 90 top
R817  10K  [RC0402]  148.34 106.17 90 top
R818  10K  [RC0402]  135.64 104.27 270 top
R821  @10K  [RC0402]  147.45 99.95 0 top
R822  10K  [RC0402]  148.46 99.95 180 top
R828  10K  [RC0402]  149.1 89.15 90 top
R829  10K  [RC0402]  152.27 90.17 90 top
R842  @33  [RC0402]  176.2 58.91 0 top
R843  0  [RC0402]  187.4 47.65 180 bottom
R844  @33  [RC0402]  170.95 75.35 0 top
R845  10  [RC0402]  204.11 43.15 180 top
R846  33  [RC0402]  149.1 88.14 90 top
R847  33  [RC0402]  149.1 90.17 90 top
R848  10K  [RC0402]  206.53 99.48 90 bottom
R849  4.7K  [RC0402]  199.67 100.55 270 top
R853  @33  [RC0402]  163.07 116.71 0 top
R855  @10K  [RC0402]  139.32 97.03 0 top
R856  @10K  [RC0402]  140.34 97.03 0 top
R857  10K  [RC0402]  141.35 97.03 0 top
R858  33  [RC0402]  142.37 99.95 0 top
R859  33  [RC0402]  143.38 99.95 0 top
R860  33  [RC0402]  145.41 99.95 0 top
R862  @10K  [RC0402]  142.37 97.03 0 top
R863  @10K  [RC0402]  143.38 97.03 0 top
R864  10K  [RC0402]  145.41 97.03 0 top
R868  220ohm  [RC0402]  131.57 84.71 90 bottom
R869  1000  [RC0402]  197.1 22.78 0 bottom
R870  33  [RC0402]  171.98 76.26 180 top
R871  33  [RC0402]  205.29 73.61 270 top
R872  33  [RC0402]  205.29 72.59 270 top
R875  100  [RC0402]  194.77 76.05 90 top
R876  0  [RC0402]  189.84 72.29 0 top
R877  @4.7K  [RC0402]  89.15 39.55 270 bottom
R878  @4.7K  [RC0402]  89.15 40.54 270 bottom
R879  @4.7K  [RC0402]  95.04 37.06 0 bottom
R880  @4.7K  [RC0402]  53.23 34.65 180 bottom
R881  0  [RC0402]  133.1 94.36 270 bottom
R882  @100K  [RC0402]  133.1 95.38 90 top
R883  100  [RC0402]  194.77 75.06 90 top
R885  33  [RC0402]  204.52 70.69 0 top
R900  0  [RC0402]  195.61 66.04 0 top
R901  10K  [RC0402]  69.6 116.46 90 top
R902  @0  [RC0402]  182.93 95.02 0 top
R905  10K  [RC0402]  77.85 116.84 90 top
R906  20  [RC0402]  106.62 94.41 180 bottom
R908  0  [RC0402]  206.06 56.12 270 bottom
R909  0  [RC0402]  202.97 51.83 180 bottom
R910  10K  [RC0402]  197.38 46.12 0 bottom
R911  0  [RC0402]  204 51.82 180 bottom
R912  0  [RC0402]  25.5 69.82 270 bottom
R913  0  [RC0402]  25.48 68.86 270 bottom
R914  10K  [RC0402]  25.48 67.89 270 bottom
R915  0  [RC0402]  25.48 66.9 270 bottom
R916  0  [RC0402]  25.48 65.91 270 bottom
R917  10K  [RC0402]  25.02 54.1 180 bottom
R918  10K  [RC0402]  31.37 55.75 90 bottom
R919  0  [RC0402]  135.76 81.03 180 top
R920  10K  [RC0402]  152.27 86.11 90 top
R921  10K  [RC0402]  188.72 72.26 180 top
R922  10K  [RC0402]  100.33 118.24 90 top
R923  0  [RC0402]  108.33 114.3 180 bottom
R924  0  [RC0402]  109.47 114.3 180 bottom
R925  0  [RC0402]  110.49 114.3 180 bottom
R926  0  [RC0402]  111.51 114.3 180 bottom
R927  0  [RC0402]  111 119.89 180 bottom
R928  0  [RC0402]  112.52 120.02 180 bottom
R929  0  [RC0402]  108.13 119.99 180 bottom
R930  0  [RC0402]  109.27 119.99 180 bottom
R931  10K  [RC0402]  111.89 109.09 270 top
R932  10K  [RC0402]  113.28 113.54 180 bottom
R933  4.7K  [RC0402]  107.31 114.3 180 bottom
R934  10K  [RC0402]  114.3 113.54 180 bottom
R935  4.7K  [RC0402]  109.73 103.63 0 bottom
R936  4.7K  [RC0402]  108.71 103.63 0 bottom
R937  0  [RC0402]  25.22 82.98 270 bottom
R938  0  [RC0402]  25.25 80.98 270 bottom
R939  0  [RC0402]  25.63 79.1 270 bottom
R940  10K  [RC0402]  25.25 81.99 270 bottom
R941  10K  [RC0402]  25.63 78.11 270 bottom
R942  10K  [RC0402]  2.92 97.03 270 bottom
R943  10K  [RC0402]  2.92 90.93 270 bottom
R944  0  [RC0402]  131.57 83.69 270 bottom
R945  0  [RC0402]  132.59 81.41 270 bottom
R946  10K  [RC0402]  28.96 78.11 180 bottom
R947  10K  [RC0402]  29.97 78.11 180 bottom
R948  10K  [RC0402]  27.94 78.11 180 bottom
R949  10K  [RC0402]  104.95 110.72 0 top
R950  10K  [RC0402]  105.94 110.95 0 top
R951  10K  [RC0402]  106.1 116.71 0 top
R952  0  [RC0402]  29.84 46.99 270 bottom
R953  10K  [RC0402]  30.35 45.47 180 bottom
R954  @10K  [RC0402]  172.72 19.05 180 bottom
R955  @10K  [RC0402]  171.96 21.21 180 bottom
R956  1M(1%)  [RC0603]  143.51 81.92 270 top
R957  4.99K  [RC0603]  147.07 80.14 180 top
R960  @10K  [RC0402]  134.24 88.39 180 bottom
R961  10K  [RC0402]  131.19 86.49 0 bottom
R962  0  [RC0603]  144.27 79.63 180 top
R963  @0  [RC0603]  149.73 99.95 0 top
R970  @10K  [RC0402]  152.27 87.12 90 top
R972  0  [RC0603]  149.1 86.87 270 top
R975  1K  [RC0402]  144.4 97.03 180 top
R976  1K  [RC0402]  133.1 93.34 270 top
R977  1K  [RC0402]  133.1 92.33 270 top
R978  1K  [RC0402]  132.59 86.61 90 bottom
R979  100K  [RC0402]  133.1 94.36 90 top
R982  @10K  [RC0402]  168.28 105.03 180 top
R989  33  [RC0402]  136.27 97.03 180 top
R999  10K  [RC0402]  142.37 99.95 180 bottom
R1001  10K  [RC0402]  143.38 99.95 180 bottom
R1003  10K  [RC0402]  139.32 99.95 0 top
R1005  10K  [RC0402]  140.34 99.95 0 top
R1007  @10K  [RC0402]  141.35 99.95 0 top
R1009  @10K  [RC0402]  144.4 99.95 0 top
R1011  @10K  [RC0402]  146.43 99.95 0 top
R1012  @10K  [RC0402]  146.43 97.03 0 top
R1031  @10K  [RC0402]  138.81 81.03 180 top
R1033  @10K  [RC0402]  136.78 81.03 180 top
R1034  10K  [RC0402]  138.81 78.49 180 top
R1035  @10K  [RC0402]  137.79 81.03 180 top
R1037  10K  [RC0402]  149.1 94.23 270 top
R1038  @10K  [RC0402]  152.27 94.23 270 top
R1039  10K  [RC0402]  149.1 92.2 270 top
R1040  @10K  [RC0402]  152.27 92.2 270 top
R1041  10K  [RC0402]  149.1 93.22 270 top
R1042  @10K  [RC0402]  152.27 93.22 270 top
R1043  @10K  [RC0402]  152.27 91.19 270 top
R1044  10K  [RC0402]  149.1 91.19 270 top
R1045  @10K  [RC0402]  160.02 119.63 0 bottom
R1046  10K  [RC0402]  135.64 107.31 270 top
R1047  @10K  [RC0402]  148.34 105.16 90 top
R1048  @10K  [RC0402]  121.16 58.55 270 top
R1049  @10K  [RC0402]  116.2 41.02 0 bottom
R1050  @10K  [RC0402]  117.6 42.16 180 bottom
R1051  @10K  [RC0402]  116.74 46.15 90 top
R1052  @10K  [RC0402]  119.25 38.63 180 top
R1053  @10K  [RC0402]  117.25 37.11 270 top
R1054  @10K  [RC0402]  198.55 36.55 270 top
R1055  @0  [RC0402]  175.01 13.46 90 top
R1056  4.7K  [RC0402]  29.72 70.74 270 bottom
R1057  10K  [RC0402]  44.32 106.81 0 bottom
R1058  @10K  [RC0402]  44.32 109.86 180 bottom
R1059  @10K  [RC0402]  43.05 106.81 0 bottom
R1060  10K  [RC0402]  43.05 109.86 180 bottom
R1061  10K  [RC0402]  41.78 106.81 0 bottom
R1062  @10K  [RC0402]  41.78 109.86 180 bottom
R1063  @10K  [RC0402]  40.51 106.81 0 bottom
R1064  10K  [RC0402]  40.77 109.86 180 bottom
R1065  @10K  [RC0402]  2.92 100.08 270 bottom
R1066  @10K  [RC0402]  2.92 93.98 270 bottom
R1067  10K  [RC0402]  38.48 106.81 180 bottom
R1068  10K  [RC0402]  37.47 106.81 180 bottom
R1069  0  [RC0402]  32.13 60.33 270 bottom
R1070  0  [RC0402]  33.02 54.86 0 bottom
R1071  @10K  [RC0402]  27.94 81.28 180 bottom
R1072  @10K  [RC0402]  28.96 81.28 180 bottom
R1073  @0  [RC0402]  184.66 50.04 270 top
R1074  @0  [RC0402]  184.66 48.77 270 top
R1075  @0  [RC0402]  184.66 51.31 270 top
R1076  @0  [RC0402]  184.66 55.75 270 top
R1077  10K  [RC0402]  35.43 106.81 180 bottom
R1078  10K  [RC0402]  45.09 112.78 0 top
R1079  10K  [RC0402]  46.35 112.78 0 top
R1080  10K  [RC0402]  43.94 112.78 180 top
R1081  @10K  [RC0402]  43.94 110.62 180 top
R1082  0  [RC0402]  178.18 23.24 0 bottom
R1083  0  [RC0402]  169.8 23.37 180 bottom
R1084  0  [RC0402]  180.47 18.16 0 top
R1085  @0  [RC0402]  179.07 25.78 270 top
R1086  @0  [RC0402]  192.79 31.11 90 bottom
R1087  4.7K  [RC0402]  42.8 26.92 0 top
R1088  10K  [RC0402]  172.09 38.99 270 bottom
R1089  @10K  [RC0402]  37.08 108.33 270 bottom
R1090  @10K  [RC0402]  45.09 110.62 0 top
R1091  @10K  [RC0402]  46.35 110.62 0 top
R1092  @33ohm  [RC0402]  130.3 97.16 270 top
R1093  @33ohm  [RC0402]  130.3 98.3 270 top
R1094  @49.9ohm  [RC0402]  132.08 98.68 0 top
R1095  @49.9ohm  [RC0402]  132.08 96.77 180 top
R1096  0  [RC0402]  118.49 93.09 90 top
R1097  0  [RC0402]  2.92 101.09 90 bottom
R1098  @0  [RC0402]  2.92 102.11 90 bottom
R1099  0  [RC0402]  2.92 95 90 bottom
R1100  @0  [RC0402]  2.92 96.01 90 bottom
R1101  0  [RC0402]  2.92 98.04 90 bottom
R1102  @0  [RC0402]  2.92 99.06 90 bottom
R1103  0  [RC0402]  2.92 91.95 90 bottom
R1104  @0  [RC0402]  2.92 92.96 90 bottom
R1105  @0  [RC0402]  39.75 109.86 180 bottom
R1106  0  [RC0402]  39.5 106.81 0 bottom
R1107  @0  [RC0402]  38.73 109.86 180 bottom
R1108  0  [RC0402]  36.45 106.81 0 bottom
R1109  0  [RC0402]  29.46 55.63 270 bottom
R1110  0  [RC0402]  25.02 55.63 270 bottom
R1111  0  [RC0402]  37.08 121.03 180 bottom
R1112  0  [RC0402]  34.8 121.03 180 bottom
R1113  0  [RC0402]  37.72 109.86 180 bottom
R1114  0  [RC0402]  35.94 121.03 0 bottom
SW1  SW_3  [SW_PUSH_3D15X1D85_4SP_3D5W2D8L]  184.91 4.96 180 top
SW2  SW_3  [SW_PUSH_3D15X1D85_4SP_3D5W2D8L]  189.23 4.96 180 top
TP1  @NCA  [TP_30C0D0C]  182.19 93.28 90 top
TP2  @NCA  [TP_30C0D0C]  182.55 92.04 90 top
TP4  T POINT R  [TP_30C0D0C]  207.19 53.4 180 top
TP5  T POINT R  [TP_30C0D0C]  207.14 52.26 0 top
TP7  T POINT R  [TP_30C0D0C]  207.22 48.48 0 top
TP9  @NCA  [TP_30C0D0C]  75.46 21.4 0 top
TP10  @NCA  [TP_30C0D0C]  75.48 20.26 0 top
TP11  @T POINT R  [TP_30C0D0C]  139.98 10.59 0 top
TP12  @T POINT R  [TP_30C0D0C]  139.83 5.66 0 top
TP14  T POINT R  [TP_30C0D0C]  92.33 91.11 0 bottom
TP15  T POINT R  [TP_30C0D0C]  94.71 90.58 180 bottom
TP16  T POINT R  [TP_30C0D0C]  93.51 90.53 180 bottom
TP17  T POINT R  [TP_30C0D0C]  102.49 89.07 180 bottom
TP18  T POINT R  [TP_30C0D0C]  99.31 90.14 180 bottom
TP19  T POINT R  [TP_30C0D0C]  91.06 89.76 0 bottom
TP20  T POINT R  [TP_30C0D0C]  98.78 88.67 0 bottom
TP21  T POINT R  [TP_30C0D0C]  92.63 84.96 0 bottom
TP22  T POINT R  [TP_30C0D0C]  95.07 85.1 0 bottom
TP23  T POINT R  [TP_30C0D0C]  80.11 84.15 180 bottom
TP24  T POINT R  [TP_30C0D0C]  80.16 82.6 180 bottom
TP25  T POINT R  [TP_30C0D0C]  93.27 78.87 180 bottom
TP26  T POINT R  [TP_30C0D0C]  92.99 75.16 180 bottom
TP27  T POINT R  [TP_30C0D0C]  105.28 74.97 180 bottom
TP28  T POINT R  [TP_30C0D0C]  112.01 74.84 180 bottom
TP29  T POINT R  [TP_30C0D0C]  110.85 74.83 180 bottom
TP30  T POINT R  [TP_30C0D0C]  111.2 70.91 180 bottom
TP31  T POINT R  [TP_30C0D0C]  101.24 62.74 0 bottom
TP32  T POINT R  [TP_30C0D0C]  114.4 58.09 180 bottom
TP33  @T POINT R  [TP_30C0D0C]  57.58 21.72 270 bottom
TP34  @NCA  [TP_30C0D0C]  119.81 19.42 0 bottom
TP35  @NCA  [TP_30C0D0C]  87.18 21.28 180 bottom
TP36  @NCA  [TP_30C0D0C]  120.72 18.5 0 bottom
TP37  @NCA  [TP_30C0D0C]  87.89 20.36 180 bottom
TP50  T POINT R  [TP_30C0D0C]  189.23 67.06 0 top
TP51  T POINT R  [TP_30C0D0C]  192.2 68.38 0 top
TP60  T POINT R  [TP_30C0D0C]  194.08 72.19 0 top
TP61  T POINT R  [TP_30C0D0C]  194.03 70.23 0 top
U1  128Mb  [SOIC_1D27X7D25_8SP_5D23WL2D16H]  99.92 114.5 180 top
U2  NC7SB3157P6X  [SC70_D65X1D9_6SP_1D25W2LD95H]  60.89 113.81 90 top
U4  TPS54426PWPR  [TSSOP_D65X5D775_14SP_4D4W5L_G1]  125.68 110.68 180 top
U5  553MILFT(Cu)  [SOIC_1D27X5D165_8SP_3D9W4D9L]  159.44 117.02 90 top
U6  WGI210IT  [QFN_D5X9D_64SP_9WL1H_3D4SQ]  140.84 88.77 270 top
U7  SN74CBTLV3257PWR  [TSSOP_D65X5D8_16SP_5D1L]  202.14 96.69 0 top
U8  TPS74701DRCR  [DFN_D5X3D_10SP_3WL1H_G1]  143.54 69.83 90 top
U9  CPU_INTEL_Broadwell-DE_1519  [BGA_D7_12C_14C_1667SP_37D5WL_1]  95.38 73.89 180 top
U10  74AVCH8T245BQ  [QFN_D5X3D5X5D5_24SP_5D5W3D5L]  174.9 71.26 0 top
U11  TPS74701DRCR  [DFN_D5X3D_10SP_3WL1H_G1]  130.46 71.93 0 top
U12  5M1270ZF256I5N  [FBGA_1D_20C_256SP_17WL]  196.09 54.61 0 top
U13  74AVCH8T245BQ  [QFN_D5X3D5X5D5_24SP_5D5W3D5L]  174.95 63.99 0 top
U14  74AVCH8T245BQ  [QFN_D5X3D5X5D5_24SP_5D5W3D5L]  174.95 52.4 0 top
U15  TPS54426PWPR  [TSSOP_D65X5D775_14SP_4D4W5L_G1]  168.73 33.68 180 top
U16  32Mb  [SOIC_1D27X7D25_8SP_5D23WL2D16H]  123.32 50.75 0 top
U17  SLB 9665XT2.0 FW5.63  [TSSOP_D65X5D8_28SP_4D4W9D7L1D2H]  174.86 19.56 0 top
U18  74AVCH4T245BQ  [QFN_D5X2D5X3D5_16SP_3D5W2D5L]  116.09 40.79 270 top
U19  2Kb  [SOIC_1D27X5D16_8SP_3D9W4D925L]  185.46 20.98 180 top
U20  LM75BD  [SO8_1D27X5D3_8SP_3D9W4D9L]  141.6 111 0 top
U21  QS3VH126QG  [SSOP_D635X5D355_16SP_3D91W4D9L]  195.29 17.15 270 top
U22  TPS54426PWPR  [TSSOP_D65X5D775_14SP_4D4W5L_G1]  158.71 70.4 0 top
U23  TPS54426PWPR  [TSSOP_D65X5D775_14SP_4D4W5L_G1]  30.33 21.81 180 top
U24  IR3556MTRPBF  [QFN_D5_32SP_6WL_IOR]  118.03 18.85 180 top
U25  IR3556MTRPBF  [QFN_D5_32SP_6WL_IOR]  85.14 20.7 180 top
U26  IR3556MTRPBF  [QFN_D5_32SP_6WL_IOR]  70.76 20.5 180 top
U27  TPS54426PWPR  [TSSOP_D65X5D775_14SP_4D4W5L_G1]  152.23 38.51 90 top
U28  IR3584MTRPBF  [QFN_D4X5D_40SP_5WLD85H]  75.41 8.71 0 top
U29  IR3570AMTRPBF+CODE  [QFN_D4X5D_40SP_5WLD85H]  58.04 6.35 270 top
U30  N-CH  [QFN_D65X2D_6SP_2WL1H]  104.94 5.67 270 top
U31  128Mb  [SOIC_1D27X7D25_8SP_5D23WL2D16H]  99.92 114.5 0 bottom
U32  NC7SB3157P6X  [SC70_D65X1D9_6SP_1D25W2LD95H]  60.89 113.83 270 bottom
U33  PCA9548PW  [TSSOP_D65X5D775_24SP_4D4W7D8L]  22.83 93.59 90 bottom
U34  74AVCH4T245BQ  [QFN_D5X2D5X3D5_16SP_3D5W2D5L]  173.28 83.8 90 bottom
U35  AX6631SA  [SOP_1D27X5D24_8SP_5L]  168.51 33.35 270 bottom
U36  PCA9617ADP  [SOP_D65X4D35_8SP_3WL]  92.3 41.63 270 bottom
U37  DC_DC_TI_TPS51200  [QFN_D5X2D95_11SP_3D15WL]  41.83 30 90 bottom
U38  SN74AVC1T45DBVR  [SOT23_6SP_D95]  167.4 109.99 180 top
U39  W25Q16JVSSIQ 16Mb  [SOIC_1D27X7D25_8SP_5D23WL2D16H]  141.86 104.78 180 top
U40  NC7SB3157P6X  [SC70_D65X1D9_6SP_1D25W2LD95H]  28.7 57.53 90 bottom
U41  NC7SB3157P6X  [SC70_D65X1D9_6SP_1D25W2LD95H]  25.4 57.53 90 bottom
U42  NC7SB3157P6X  [SC70_D65X1D9_6SP_1D25W2LD95H]  102.87 118.75 90 top
U43  SN74CBTLV3257PWR  [TSSOP_D65X5D8_16SP_5D1L]  110.02 114.66 90 top
U44  NC7SB3157P6X  [SC70_D65X1D9_6SP_1D25W2LD95H]  108.97 108.2 270 top
U45  PCA9641PWJ  [TSSOP_D65X5D775_16SP_4D4W5L1D2H]  40.89 116.08 270 bottom
X1  32.768KHZ  [XTAL_2D5_2SP_1D5W3D2L0D9H]  95.63 99.82 180 top

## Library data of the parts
BA1 = HOLDER_1
C1-C42 C51 C52 C54 C55 C57-C61 C63-C70 C74-C78 C81-C84 C87-C121 C123 C124 C126-C130 C134-C153 C155 C156 C158-C166 C168-C228 C231-C260 C262-C278 C281-C450 C452-C616 C619-C640 C643 C644 C647-C652 C664 C665 C701-C704 C707 C708 C841 C900-C902 C904 C905 C908-C915 C925-C931 C933-C939 C941-C945 C959-C961 C963 C964 C967-C976 = C_NP
C125 C131-C133 C157 C167 C279 C280 C903 C906 C907 C965 C966 = C_P
C154 = C
CONN1 = CONN_USB_FEMALE_5P_G6
CONN2 CONN12 CONN17 = PINSTICK_MALE_3PX1R
CONN3 = PIN HEADER_MALE_4PX2R
CONN4 CONN11 = BTB_FEMALE_SMD60
CONN5 = PINSTICK_MALE_5PX2R_VOID10
CONN6 = MSATA_FEMALE_52P_G2
CONN7 CONN8 = SODIMM_DDR4_FEMALE_260P_G2
CONN9 = PINSTICK_MALE_5PX2R
CONN13 = M.2_FEMALE_75P_G2
CONN14 = BMM CONN
CONN15 = CONN_WAFER_MALE_8PX1R_G2
CONN16 = BTB_MALE_SMD120
CONN18 = PINSTICK_MALE_4PX1R
D1 = DIODE1_1
H1 H2 H7-H9 = SCREW_8_1
HS1 = HEATSINK_4PIN
HSB1 = HEATSINK_4PIN_NC
L1 L3-L10 L12 L19 L21-L23 L25-L27 L30-L37 L41 L42 L49 L50 = BEAD
L2 L11 L13-L18 L20 L24 = POWER CHOKE
L28 L29 = BEAD: room: 5
LED1-LED11 LED13-LED18 = LED1_1
LED19 = LED2_1
NUT1-NUT3 = NUT_1
OSC1 = OSC_10
OSC2 = OSC_1
OSC4 = OSC_21
OSC5 OSC6 = XTAL_2
Q1 Q2 Q4-Q6 Q14 = NMOS1_9
Q3 = DIODE2_1
Q7 = SCHOTTKY2_2
Q8 Q11-Q13 Q16 = NMOS1_1
Q9 Q10 = TTL_NXP_SN74AVC1T45GW
QFN1 = DRIVER_IR_IR3553
R4-R15 R17-R75 R77-R80 R82-R159 R164 R169 R171-R173 R180 R182 R184-R189 R192-R226 R228-R296 R298 R300-R313 R315-R319 R321-R325 R327-R376 R378-R427 R429-R433 R435-R471 R473-R483 R485-R587 R589 R590 R592-R607 R609 R610 R613-R716 R719 R720 R723-R780 R783-R803 R806-R809 R811-R818 R821 R822 R828 R829 R842-R848 R853 R855-R860 R862-R864 R869-R872 R875-R883 R885 R900-R902 R905 R906 R908-R932 R934-R957 R960-R963 R970 R972 R975-R979 R982 R989 R999 R1001 R1003 R1005 R1007 R1009 R1011 R1012 R1031 R1033-R1035 R1037-R1114 = R: tolerance: 1%
R163 R297 R299 R314 R611 R612 R717 R718 R721 R722 R868 = R
R320 R326 = NTC
R377 = R: tolerance: 1 %
R608 = R: room: 71
R849 R933 = R: tolerance: 1%; room: U83
SW1 SW2 = SW_3
TP1 TP2 TP9 TP10 TP34-TP37 = NCA
TP4 TP5 TP7 TP11 TP12 TP14-TP33 TP50 TP51 TP60 TP61 = T POINT R
U1 U31 = FLASH_WINBOND_W25Q128FV
U2 U32 U41 U42 U44 = MUX_FAIRCHILD_NC7SB3157P6X
U4 U15 U22 U23 U27 = DC_DC_TI_TPS54426
U5 = CLK_IDT_ICS553
U6 = LAN_CHIP_INTEL_I210_copper
U7 U43 = TTL_TI_SN74CBTLV3257_1
U8 U11 = LDO_TI_TPS74701
U9 = CPU_INTEL_Broadwell-DE
U10 U13 U14 = TTL_NXP_74AVCH8T245BQ
U12 = CPLD_ALTERA_5M1270_FBGA256
U16 = FLASH_WINBOND_W25Q32FV
U17 = ASIC_INFINEON_SLB9665TT2.0
U18 U34 = TTL_NXP_74AVCH4T245BQ
U19 = EEPROM_ATMEL_AT24C02D
U20 = TEMP MINOTOR_NXP_LM75BD
U21 = CLK_IDT_IDTQS3VH126_QSOP16
U24-U26 = DRIVER_IR_IR3556
U28 = PWMCTRL_IR_IR3584
U29 = PWMCTRL_IR_IR3570A
U30 = NMOS_IR_IRFHS8242TR2PBF
U33 = I2C_PHILIPS_PCA9548
U35 = LDO_AXELITE_AX6631
U36 = I2C_NXP_PCA9517A
U37 = DC_DC_TI_TPS51200
U38 = LOGIC_TI_SN74AVC1T45
U39 = FLASH_WINBOND_W25Q16JV
U40 = MUX_FAIRCHILD_NC7SB3157P6X_0
U45 = I2C_NXP_PCA9641PW
X1 = XTAL_1

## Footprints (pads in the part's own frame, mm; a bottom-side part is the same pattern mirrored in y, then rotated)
BATTERY_14D8_2SP_15D5W10D39L
  round 0.762 hole 0.762 unplated: (0,-4)
  round 1.092 hole 1.092 unplated: (0,4)
  rect 2.032x1.524 smd: 1(7.4,0) 2(-7.4,0)
BEAD_3D58_2SP_3D05W4D06L2D62H
  rect 1.524x2.794 smd: 1(0,1.79) 2(0,-1.79)
BGA_D7_12C_14C_1667SP_37D5WL_1
  round 0.508 smd: (-19.75,19.75) (19.75,-19.75)
  round 0.381 smd: A3(-18.064,-16.642) A5(-18.064,-15.931) A74(-18.064,15.931) A76(-18.064,16.642) AA9(-8.172,-14.166) AA12(-8.172,-12.507) AA14(-8.172,-11.707) AA16(-8.172,-10.907) AA18(-8.172,-10.107) AA19(-8.172,-9.307) AA21(-8.172,-8.506) AA23(-8.172,-7.706) AA25(-8.172,-6.906) AA27(-8.172,-6.106) AA28(-8.172,-5.306) AA30(-8.172,-4.506) AA53(-8.172,5.758) AA55(-8.172,6.558) AA56(-8.172,7.358) AA58(-8.172,8.158) AA60(-8.172,8.959) AA62(-8.172,9.759) AA66(-8.172,11.59) AA69(-8.172,13.307) AA72(-8.172,15.024) AC7(-7.677,-15.024) AC11(-7.677,-13.307) AC12(-7.372,-12.507) AC14(-7.372,-11.707) AC16(-7.372,-10.907) AC18(-7.372,-10.107) AC19(-7.372,-9.307) AC21(-7.372,-8.506) AC23(-7.372,-7.706) AC25(-7.372,-6.906) AC27(-7.372,-6.106) AC28(-7.372,-5.306) AC30(-7.372,-4.506) AC53(-7.372,5.758) AC55(-7.372,6.558) AC56(-7.372,7.358) AC58(-7.372,8.158) AC60(-7.372,8.959) AC62(-7.372,9.759) AC64(-7.677,10.732) AC67(-7.677,12.449) AC71(-7.677,14.166) AD9(-7.182,-14.166) AD66(-7.182,11.59) AD69(-7.182,13.307) AD72(-7.182,15.024) AE7(-6.687,-15.024) AE11(-6.687,-13.307) AE12(-6.572,-12.507) AE14(-6.572,-11.707) AE16(-6.572,-10.907) AE18(-6.572,-10.107) AE19(-6.572,-9.307) AE21(-6.572,-8.506) AE23(-6.572,-7.706) AE25(-6.572,-6.906) AE27(-6.572,-6.106) AE28(-6.572,-5.306) AE30(-6.572,-4.506) AE53(-6.572,5.758) AE55(-6.572,6.558) AE56(-6.572,7.358) AE58(-6.572,8.158) AE60(-6.572,8.959) AE62(-6.572,9.759) AE64(-6.687,10.732) AE67(-6.687,12.449) AE71(-6.687,14.166) AF9(-6.191,-14.166) AF66(-6.191,11.59) AF69(-6.191,13.307) AF72(-6.191,15.024) AG7(-5.696,-15.024) AG11(-5.696,-13.307) AG12(-5.772,-12.507) AG14(-5.772,-11.707) AG16(-5.772,-10.907) AG18(-5.772,-10.107) AG19(-5.772,-9.307) AG21(-5.772,-8.506) AG23(-5.772,-7.706) AG25(-5.772,-6.906) AG27(-5.772,-6.106) AG28(-5.772,-5.306) AG30(-5.772,-4.506) AG53(-5.772,5.758) AG55(-5.772,6.558) AG56(-5.772,7.358) AG58(-5.772,8.158) AG60(-5.772,8.959) AG62(-5.772,9.759) AG64(-5.696,10.732) AG67(-5.696,12.449) AG71(-5.696,14.166) AH9(-5.201,-14.166) AH12(-4.972,-12.507) AH14(-4.972,-11.707) AH16(-4.972,-10.907) AH18(-4.972,-10.107) AH19(-4.972,-9.307) AH21(-4.972,-8.506) AH23(-4.972,-7.706) AH25(-4.972,-6.906) AH27(-4.972,-6.106) AH28(-4.972,-5.306) AH30(-4.972,-4.506) AH53(-4.972,5.758) AH55(-4.972,6.558) AH56(-4.972,7.358) AH58(-4.972,8.158) AH60(-4.972,8.959) AH62(-4.972,9.759) AH66(-5.201,11.59) AH69(-5.201,13.307) AH72(-5.201,15.024) AJ7(-4.705,-15.024) AJ11(-4.705,-13.307) AJ64(-4.705,10.732) AJ67(-4.705,12.449) AJ71(-4.705,14.166) AK9(-4.21,-14.166) AK12(-4.172,-12.507) AK14(-4.172,-11.707) AK16(-4.172,-10.907) AK18(-4.172,-10.107) AK19(-4.172,-9.307) AK21(-4.172,-8.506) AK23(-4.172,-7.706) AK25(-4.172,-6.906) AK27(-4.172,-6.106) AK28(-4.172,-5.306) AK30(-4.172,-4.506) AK53(-4.172,5.758) AK55(-4.172,6.558) AK56(-4.172,7.358) AK58(-4.172,8.158) AK60(-4.172,8.959) AK62(-4.172,9.759) AK66(-4.21,11.59) AK69(-4.21,13.307) AK72(-4.21,15.024) AL7(-3.715,-15.024) AL11(-3.715,-13.307) AL64(-3.715,10.732) AL67(-3.715,12.449) AL71(-3.715,14.166) AM9(-3.219,-14.166) AM12(-3.372,-12.507) AM14(-3.372,-11.707) AM16(-3.372,-10.907) AM18(-3.372,-10.107) AM19(-3.372,-9.307) AM21(-3.372,-8.506) AM23(-3.372,-7.706) AM25(-3.372,-6.906) AM27(-3.372,-6.106) AM28(-3.372,-5.306) AM30(-3.372,-4.506) AM53(-3.372,5.758) AM55(-3.372,6.558) AM56(-3.372,7.358) AM58(-3.372,8.158) AM60(-3.372,8.959) AM62(-3.372,9.759) AM66(-3.219,11.59) AM69(-3.219,13.307) AM72(-3.219,15.024) AN7(-2.724,-15.024) AN11(-2.724,-13.307) AN64(-2.724,10.732) AN67(-2.724,12.449) AN71(-2.724,14.166) AP9(-2.229,-14.166) AP12(-2.572,-12.507) AP14(-2.572,-11.707) AP16(-2.572,-10.907) AP18(-2.572,-10.107) AP19(-2.572,-9.307) AP21(-2.572,-8.506) AP23(-2.572,-7.706) AP25(-2.572,-6.906) AP27(-2.572,-6.106) AP28(-2.572,-5.306) AP30(-2.572,-4.506) AP53(-2.572,5.758) AP55(-2.572,6.558) AP56(-2.572,7.358) AP58(-2.572,8.158) AP60(-2.572,8.959) AP62(-2.572,9.759) AP66(-2.229,11.59) AP69(-2.229,13.307) AP72(-2.229,15.024) AR7(-1.734,-15.024) AR11(-1.734,-13.307) AR12(-1.772,-12.507) AR14(-1.772,-11.707) AR16(-1.772,-10.907) AR18(-1.772,-10.107) AR19(-1.772,-9.307) AR21(-1.772,-8.506) AR23(-1.772,-7.706) AR25(-1.772,-6.906) AR27(-1.772,-6.106) AR28(-1.772,-5.306) AR30(-1.772,-4.506) AR53(-1.772,5.758) AR55(-1.772,6.558) AR56(-1.775,7.358) AR60(-1.734,9.014) AR64(-1.734,10.732) AR67(-1.734,12.449) AR71(-1.734,14.166) AU9(-1.238,-14.166) AU12(-0.972,-12.507) AU14(-0.972,-11.707) AU16(-0.972,-10.907) AU18(-0.972,-10.107) AU19(-0.972,-9.307) AU21(-0.972,-8.506) AU23(-0.972,-7.706) AU25(-0.972,-6.906) AU27(-0.972,-6.106) AU28(-0.972,-5.306) AU30(-0.972,-4.506) AU53(-0.972,5.758) AU55(-0.972,6.558) AU56(-0.975,7.358) AU58(-1.238,8.156) AU62(-1.238,9.873) AU66(-1.238,11.59) AU69(-1.238,13.307) AU72(-1.238,15.024) AV7(-0.743,-15.024) AV11(-0.743,-13.307) AV60(-0.743,9.014) AV64(-0.743,10.732) AV67(-0.743,12.449) AV71(-0.743,14.166) AW9(-0.248,-14.166) AW12(-0.171,-12.507) AW14(-0.171,-11.707) AW16(-0.171,-10.907) AW18(-0.171,-10.107) AW19(-0.171,-9.307) AW21(-0.171,-8.506) AW23(-0.171,-7.706) AW25(-0.171,-6.906) AW27(-0.171,-6.106) AW28(-0.171,-5.306) AW30(-0.171,-4.506) AW55(-0.171,6.558) AW56(-0.174,7.358) AW58(-0.248,8.156) AW62(-0.248,9.873) AW66(-0.248,11.59) AW69(-0.248,13.307) AW72(-0.248,15.024) AY7(0.248,-15.024) AY11(0.248,-13.307) AY60(0.248,9.014) AY64(0.248,10.732) AY67(0.248,12.449) AY71(0.248,14.166) B2(-17.353,-17.353) B77(-17.353,17.353) BA9(0.743,-14.166) BA12(0.629,-12.507) BA14(0.629,-11.707) BA16(0.629,-10.907) BA18(0.629,-10.107) BA19(0.629,-9.307) BA21(0.629,-8.506) BA23(0.629,-7.706) BA25(0.629,-6.906) BA27(0.629,-6.106) BA28(0.629,-5.306) BA30(0.629,-4.506) BA56(0.626,7.358) BA58(0.743,8.156) BA62(0.743,9.873) BA66(0.743,11.59) BA69(0.743,13.307) BA72(0.743,15.024) BB7(1.238,-15.024) BB11(1.238,-13.307) BB12(1.429,-12.507) BB14(1.429,-11.707) BB16(1.429,-10.907) BB18(1.429,-10.107) BB19(1.429,-9.307) BB21(1.429,-8.506) BB23(1.429,-7.706) BB25(1.429,-6.906) BB27(1.429,-6.106) BB28(1.429,-5.306) BB30(1.429,-4.506) BB32(1.429,-3.806) BB33(1.429,-3.106) BB35(1.429,-2.406) BB36(1.429,-1.672) BB56(1.426,7.358) BB60(1.238,9.014) BB64(1.238,10.732) BB67(1.238,12.449) BB71(1.238,14.166) BC9(1.734,-14.166) BC58(1.734,8.156) BC62(1.734,9.873) BC66(1.734,11.59) BC69(1.734,13.307) BC72(1.734,15.024) BD7(2.229,-15.024) BD11(2.229,-13.307) BD14(2.229,-11.59) BD18(2.229,-9.873) BD22(2.229,-8.156) BD26(2.229,-6.439) BD30(2.229,-4.722) BD33(2.229,-3.005) BD36(2.029,-2.039) BD37(2.026,-1.306) BD56(2.226,7.358) BD60(2.229,9.014) BD64(2.229,10.732) BD67(2.229,12.449) BD71(2.229,14.166) BE9(2.724,-14.166) BE13(2.724,-12.449) BE16(2.724,-10.732) BE20(2.724,-9.014) BE24(2.724,-7.297) BE28(2.724,-5.58) BE32(2.724,-3.863) BE35(2.724,-2.146) BE37(2.726,-1.306) BE58(2.724,8.156) BE62(2.724,9.873) BE66(2.724,11.59) BE69(2.724,13.307) BE72(2.724,15.024) BF7(3.219,-15.024) BF11(3.219,-13.307) BF14(3.219,-11.59) BF18(3.219,-9.873) BF22(3.219,-8.156) BF26(3.219,-6.439) BF30(3.219,-4.722) BF33(3.219,-3.005) BF56(3.026,7.358) BF60(3.219,9.014) BF64(3.219,10.732) BF67(3.219,12.449) BF71(3.219,14.166) BG9(3.715,-14.166) BG13(3.715,-12.449) BG16(3.715,-10.732) BG20(3.715,-9.014) BG24(3.715,-7.297) BG28(3.715,-5.58) BG32(3.715,-3.863) BG35(3.715,-2.146) BG37(3.426,-1.306) BG58(3.715,8.156) BG62(3.715,9.873) BG66(3.715,11.59) BG69(3.715,13.307) BG72(3.715,15.024) BH7(4.21,-15.024) BH11(4.21,-13.307) BH14(4.21,-11.59) BH18(4.21,-9.873) BH22(4.21,-8.156) BH26(4.21,-6.439) BH30(4.21,-4.722) BH33(4.21,-3.005) BH37(4.126,-1.306) BH56(3.826,7.358) BH60(4.21,9.014) BH64(4.21,10.732) BH67(4.21,12.449) BH71(4.21,14.166) BJ9(4.705,-14.166) BJ13(4.705,-12.449) BJ16(4.705,-10.732) BJ20(4.705,-9.014) BJ24(4.705,-7.297) BJ28(4.705,-5.58) BJ32(4.705,-3.863) BJ35(4.705,-2.146) BJ56(4.626,7.358) BJ58(4.705,8.156) BJ62(4.705,9.873) BJ66(4.705,11.59) BJ69(4.705,13.307) BJ72(4.705,15.024) BK37(4.826,-1.306) BL7(5.201,-15.024) BL11(5.201,-13.307) BL14(5.201,-11.59) BL18(5.201,-9.873) BL22(5.201,-8.156) BL26(5.201,-6.439) BL30(5.201,-4.722) BL33(5.201,-3.005) BL37(5.526,-1.306) BL56(5.426,7.358) BL60(5.201,9.014) BL64(5.201,10.732) BL67(5.201,12.449) BL71(5.201,14.166) BM9(5.696,-14.166) BM13(5.696,-12.449) BM16(5.696,-10.732) BM20(5.696,-9.014) BM24(5.696,-7.297) BM28(5.696,-5.58) BM32(5.696,-3.863) BM35(5.696,-2.146) BM58(5.696,8.156) BM62(5.696,9.873) BM66(5.696,11.59) BM69(5.696,13.307) BM72(5.696,15.024) BN7(6.191,-15.024) BN11(6.191,-13.307) BN14(6.191,-11.59) BN18(6.191,-9.873) BN22(6.191,-8.156) BN26(6.191,-6.439) BN30(6.191,-4.722) BN33(6.191,-3.005) BN37(6.226,-1.306) BN56(6.226,7.358) BN60(6.191,9.014) BN64(6.191,10.732) BN67(6.191,12.449) BN71(6.191,14.166) BP9(6.687,-14.166) BP13(6.687,-12.449) BP16(6.687,-10.732) BP20(6.687,-9.014) BP24(6.687,-7.297) BP28(6.687,-5.58) BP32(6.687,-3.863) BP35(6.687,-2.146) BP37(6.926,-1.306) BP56(7.026,7.358) BP58(6.687,8.156) BP62(6.687,9.873) BP66(6.687,11.59) BP69(6.687,13.307) BP72(6.687,15.024) BR7(7.182,-15.024) BR11(7.182,-13.307) BR14(7.182,-11.59) BR18(7.182,-9.873) BR22(7.182,-8.156) BR26(7.182,-6.439) BR30(7.182,-4.722) BR33(7.182,-3.005) BR60(7.182,9.014) BR64(7.182,10.732) BR67(7.182,12.449) BR71(7.182,14.166) BT9(7.677,-14.166) BT13(7.677,-12.449) BT16(7.677,-10.732) BT20(7.677,-9.014) BT24(7.677,-7.297) BT28(7.677,-5.58) BT32(7.677,-3.863) BT35(7.677,-2.146) BT37(7.627,-1.306) BT56(7.727,7.358) BT58(7.677,8.156) BT62(7.677,9.873) BT66(7.677,11.59) BT69(7.677,13.307) BT72(7.677,15.024) BU7(8.172,-15.024) BU11(8.172,-13.307) BU14(8.172,-11.59) BU18(8.172,-9.873) BU22(8.172,-8.156) BU26(8.172,-6.439) BU30(8.172,-4.722) BU33(8.172,-3.005) BU37(8.327,-1.306) BU60(8.172,9.014) BU64(8.172,10.732) BU67(8.172,12.449) BU71(8.172,14.166) BV9(8.668,-14.166) BV13(8.668,-12.449) BV16(8.668,-10.732) BV20(8.668,-9.014) BV24(8.668,-7.297) BV28(8.668,-5.58) BV32(8.668,-3.863) BV35(8.668,-2.146) BV56(8.427,7.358) BV58(8.668,8.156) BV62(8.668,9.873) BV66(8.668,11.59) BV69(8.668,13.307) BV72(8.668,15.024) BW7(9.163,-15.024) BW11(9.163,-13.307) BW14(9.163,-11.59) BW18(9.163,-9.873) BW22(9.163,-8.156) BW26(9.163,-6.439) BW30(9.163,-4.722) BW33(9.163,-3.005) BW37(9.027,-1.306) BW39(8.958,-0.607) BW40(8.958,0.093) BW42(8.958,0.793) BW43(8.958,1.493) BW45(9.258,2.226) BW47(9.258,3.026) BW49(9.258,3.827) BW50(9.258,4.627) BW52(9.158,5.427) BW54(8.958,6.127) BW55(8.958,6.877) BW60(9.163,9.014) BW64(9.163,10.732) BW67(9.163,12.449) BW71(9.163,14.166) BY9(9.658,-14.166) BY13(9.658,-12.449) BY16(9.658,-10.732) BY20(9.658,-9.014) BY24(9.658,-7.297) BY28(9.658,-5.58) BY32(9.658,-3.863) BY35(9.658,-2.146) BY39(9.658,-0.429) BY43(9.658,1.288) BY54(9.658,6.439) BY58(9.658,8.156) BY62(9.658,9.873) BY66(9.658,11.59) BY69(9.658,13.307) BY72(9.658,15.024) C1(-16.642,-18.064) C78(-16.642,18.064) CA7(10.154,-15.024) CA11(10.154,-13.307) CA14(10.154,-11.59) CA18(10.154,-9.873) CA22(10.154,-8.156) CA26(10.154,-6.439) CA30(10.154,-4.722) CA33(10.154,-3.005) CA37(10.154,-1.288) CA41(10.154,0.429) CA45(10.154,2.146) CA46(9.943,2.84) CA49(10.154,3.863) CA51(9.943,4.887) CA52(10.154,5.58) CA56(10.154,7.297) CA60(10.154,9.014) CA64(10.154,10.732) CA67(10.154,12.449) CA71(10.154,14.166) CB9(10.649,-14.166) CB13(10.649,-12.449) CB16(10.649,-10.732) CB20(10.649,-9.014) CB24(10.649,-7.297) CB28(10.649,-5.58) CB32(10.649,-3.863) CB35(10.649,-2.146) CB39(10.649,-0.429) CB43(10.649,1.288) CB47(10.649,3.005) CB51(10.649,4.722) CB54(10.649,6.439) CB58(10.649,8.156) CB62(10.649,9.873) CB66(10.649,11.59) CB69(10.649,13.307) CB72(10.649,15.024) CC7(11.144,-15.024) CC11(11.144,-13.307) CC14(11.144,-11.59) CC18(11.144,-9.873) CC22(11.144,-8.156) CC26(11.144,-6.439) CC30(11.144,-4.722) CC33(11.144,-3.005) CC37(11.144,-1.288) CC41(11.144,0.429) CC45(11.144,2.146) CC49(11.144,3.863) CC52(11.144,5.58) CC56(11.144,7.297) CC60(11.144,9.014) CC64(11.144,10.732) CC67(11.144,12.449) CC71(11.144,14.166) CD9(11.64,-14.166) CD13(11.64,-12.449) CD16(11.64,-10.732) CD20(11.64,-9.014) CD24(11.64,-7.297) CD28(11.64,-5.58) CD32(11.64,-3.863) CD35(11.64,-2.146) CD39(11.64,-0.429) CD43(11.64,1.288) CD47(11.64,3.005) CD51(11.64,4.722) CD54(11.64,6.439) CD58(11.64,8.156) CD62(11.64,9.873) CD66(11.64,11.59) CD69(11.64,13.307) CD72(11.64,15.024) CF7(12.135,-15.024) CF11(12.135,-13.307) CF14(12.135,-11.59) CF18(12.135,-9.873) CF22(12.135,-8.156) CF26(12.135,-6.439) CF30(12.135,-4.722) CF33(12.135,-3.005) CF37(12.135,-1.288) CF41(12.135,0.429) CF45(12.135,2.146) CF49(12.135,3.863) CF52(12.135,5.58) CF56(12.135,7.297) CF60(12.135,9.014) CF64(12.135,10.732) CF67(12.135,12.449) CF71(12.135,14.166) CG9(12.63,-14.166) CG13(12.63,-12.449) CG16(12.63,-10.732) CG20(12.63,-9.014) CG24(12.63,-7.297) CG28(12.63,-5.58) CG32(12.63,-3.863) CG35(12.63,-2.146) CG39(12.63,-0.429) CG43(12.63,1.288) CG47(12.63,3.005) CG51(12.63,4.722) CG54(12.63,6.439) CG58(12.63,8.156) CG62(12.63,9.873) CG66(12.63,11.59) CG69(12.63,13.307) CG72(12.63,15.024) CH7(13.125,-15.024) CH11(13.125,-13.307) CH14(13.125,-11.59) CH18(13.125,-9.873) CH22(13.125,-8.156) CH26(13.125,-6.439) CH30(13.125,-4.722) CH33(13.125,-3.005) CH37(13.125,-1.288) CH41(13.125,0.429) CH45(13.125,2.146) CH49(13.125,3.863) CH52(13.125,5.58) CH56(13.125,7.297) CH60(13.125,9.014) CH64(13.125,10.732) CH67(13.125,12.449) CH71(13.125,14.166) CJ9(13.621,-14.166) CJ13(13.621,-12.449) CJ16(13.621,-10.732) CJ20(13.621,-9.014) CJ24(13.621,-7.297) CJ28(13.621,-5.58) CJ32(13.621,-3.863) CJ35(13.621,-2.146) CJ39(13.621,-0.429) CJ43(13.621,1.288) CJ47(13.621,3.005) CJ51(13.621,4.722) CJ54(13.621,6.439) CJ58(13.621,8.156) CJ62(13.621,9.873) CJ66(13.621,11.59) CJ69(13.621,13.307) CJ72(13.621,15.024) CK7(14.116,-15.024) CK11(14.116,-13.307) CK14(14.116,-11.59) CK18(14.116,-9.873) CK22(14.116,-8.156) CK26(14.116,-6.439) CK30(14.116,-4.722) CK33(14.116,-3.005) CK37(14.116,-1.288) CK41(14.116,0.429) CK45(14.116,2.146) CK49(14.116,3.863) CK52(14.116,5.58) CK56(14.116,7.297) CK60(14.116,9.014) CK64(14.116,10.732) CK67(14.116,12.449) CK71(14.116,14.166) CL9(14.611,-14.166) CL13(14.611,-12.449) CL16(14.611,-10.732) CL20(14.611,-9.014) CL24(14.611,-7.297) CL28(14.611,-5.58) CL32(14.611,-3.863) CL35(14.611,-2.146) CL39(14.611,-0.429) CL43(14.611,1.288) CL47(14.611,3.005) CL51(14.611,4.722) CL54(14.611,6.439) CL58(14.611,8.156) CL62(14.611,9.873) CL66(14.611,11.59) CL69(14.611,13.307) CL72(14.611,15.024) CM7(15.107,-15.024) CM11(15.107,-13.307) CM14(15.107,-11.59) CM18(15.107,-9.873) CM22(15.107,-8.156) CM26(15.107,-6.439) CM30(15.107,-4.722) CM33(15.107,-3.005) CM37(15.107,-1.288) CM41(15.107,0.429) CM45(15.107,2.146) CM49(15.107,3.863) CM52(15.107,5.58) CM56(15.107,7.297) CM60(15.107,9.014) CM64(15.107,10.732) CM67(15.107,12.449) CM71(15.107,14.166) CP1(15.931,-18.064) CP78(15.931,18.064) CR1(16.642,-18.064) CR78(16.642,18.064) CU2(17.353,-17.353) CU77(17.353,17.353) CV3(18.064,-16.642) CV5(18.064,-15.931) CV74(18.064,15.931) CV76(18.064,16.642) E1(-15.931,-18.064) E78(-15.931,18.064) F9(-15.107,-14.166) F13(-15.107,-12.449) F16(-15.107,-10.732) F20(-15.107,-9.014) F24(-15.107,-7.297) F28(-15.107,-5.58) F32(-15.107,-3.863) F35(-15.107,-2.146) F39(-15.107,-0.429) F43(-15.107,1.288) F47(-15.107,3.005) F51(-15.107,4.722) F54(-15.107,6.439) F58(-15.107,8.156) F62(-15.107,9.873) F66(-15.107,11.59) F69(-15.107,13.307) F72(-15.107,15.024) H7(-14.611,-15.024) H11(-14.611,-13.307) H14(-14.611,-11.59) H18(-14.611,-9.873) H22(-14.611,-8.156) H26(-14.611,-6.439) H30(-14.611,-4.722) H33(-14.611,-3.005) H37(-14.611,-1.288) H41(-14.611,0.429) H45(-14.611,2.146) H49(-14.611,3.863) H52(-14.611,5.58) H56(-14.611,7.297) H60(-14.611,9.014) H64(-14.611,10.732) H67(-14.611,12.449) H71(-14.611,14.166) J9(-14.116,-14.166) J13(-14.116,-12.449) J16(-14.116,-10.732) J20(-14.116,-9.014) J24(-14.116,-7.297) J28(-14.116,-5.58) J32(-14.116,-3.863) J35(-14.116,-2.146) J39(-14.116,-0.429) J43(-14.116,1.288) J47(-14.116,3.005) J51(-14.116,4.722) J54(-14.116,6.439) J58(-14.116,8.156) J62(-14.116,9.873) J66(-14.116,11.59) J69(-14.116,13.307) J72(-14.116,15.024) K7(-13.621,-15.024) K11(-13.621,-13.307) K14(-13.621,-11.59) K18(-13.621,-9.873) K22(-13.621,-8.156) K26(-13.621,-6.439) K30(-13.621,-4.722) K33(-13.621,-3.005) K37(-13.621,-1.288) K41(-13.621,0.429) K45(-13.621,2.146) K49(-13.621,3.863) K52(-13.621,5.58) K56(-13.621,7.297) K60(-13.621,9.014) K64(-13.621,10.732) K67(-13.621,12.449) K71(-13.621,14.166) L9(-13.125,-14.166) L13(-13.125,-12.449) L16(-13.125,-10.732) L20(-13.125,-9.014) L24(-13.125,-7.297) L28(-13.125,-5.58) L32(-13.125,-3.863) L35(-13.125,-2.146) L39(-13.125,-0.429) L43(-13.125,1.288) L47(-13.125,3.005) L51(-13.125,4.722) L54(-13.125,6.439) L58(-13.125,8.156) L62(-13.125,9.873) L66(-13.125,11.59) L69(-13.125,13.307) L72(-13.125,15.024) M7(-12.63,-15.024) M11(-12.63,-13.307) M14(-12.63,-11.59) M18(-12.63,-9.873) M22(-12.63,-8.156) M26(-12.63,-6.439) M30(-12.63,-4.722) M33(-12.63,-3.005) M37(-12.63,-1.288) M41(-12.63,0.429) M45(-12.63,2.146) M49(-12.63,3.863) M52(-12.63,5.58) M56(-12.63,7.297) M60(-12.63,9.014) M64(-12.63,10.732) M67(-12.63,12.449) M71(-12.63,14.166) N9(-12.135,-14.166) N13(-12.135,-12.449) N16(-12.135,-10.732) N20(-12.135,-9.014) N24(-12.135,-7.297) N28(-12.135,-5.58) N32(-12.135,-3.863) N35(-12.135,-2.146) N39(-12.135,-0.429) N43(-12.135,1.288) N47(-12.135,3.005) N51(-12.135,4.722) N54(-12.135,6.439) N58(-12.135,8.156) N62(-12.135,9.873) N66(-12.135,11.59) N69(-12.135,13.307) N72(-12.135,15.024) P7(-11.64,-15.024) P11(-11.64,-13.307) P14(-11.64,-11.59) P18(-11.64,-9.873) P22(-11.64,-8.156) P26(-11.64,-6.439) P30(-11.64,-4.722) P33(-11.64,-3.005) P52(-11.64,5.58) P56(-11.64,7.297) P60(-11.64,9.014) P64(-11.64,10.732) P67(-11.64,12.449) P71(-11.64,14.166) R9(-11.144,-14.166) R13(-11.144,-12.449) R16(-11.144,-10.732) R20(-11.144,-9.014) R24(-11.144,-7.297) R28(-11.144,-5.58) R32(-11.144,-3.863) R35(-11.373,-2.243) R37(-11.373,-1.443) R39(-11.373,-0.643) R40(-11.373,0.157) R42(-11.373,0.958) R44(-11.373,1.758) R46(-11.373,2.558) R48(-11.373,3.358) R49(-11.373,4.158) R54(-11.144,6.439) R58(-11.144,8.156) R62(-11.144,9.873) R66(-11.144,11.59) R69(-11.144,13.307) R72(-11.144,15.024) T7(-10.649,-15.024) T11(-10.649,-13.307) T14(-10.649,-11.59) T18(-10.649,-9.873) T22(-10.649,-8.156) T26(-10.649,-6.439) T30(-10.649,-4.722) T33(-10.649,-3.005) T35(-10.573,-2.243) T37(-10.573,-1.443) T39(-10.573,-0.643) T40(-10.573,0.157) T42(-10.573,0.958) T44(-10.573,1.758) T46(-10.573,2.558) T48(-10.573,3.358) T49(-10.573,4.158) T51(-10.573,4.958) T53(-10.573,5.758) T56(-10.649,7.297) T60(-10.649,9.014) T64(-10.649,10.732) T67(-10.649,12.449) T71(-10.649,14.166) U9(-10.154,-14.166) U13(-10.154,-12.449) U16(-10.154,-10.732) U20(-10.154,-9.014) U24(-10.154,-7.297) U28(-10.154,-5.58) U32(-10.154,-3.863) U66(-10.154,11.59) U69(-10.154,13.307) U72(-10.154,15.024) V7(-9.658,-15.024) V11(-9.658,-13.307) V14(-9.658,-11.59) V18(-9.658,-9.873) V22(-9.658,-8.156) V26(-9.658,-6.439) V30(-9.658,-4.722) V33(-9.773,-3.043) V35(-9.773,-2.243) V37(-9.773,-1.443) V39(-9.773,-0.643) V40(-9.773,0.157) V42(-9.773,0.958) V44(-9.773,1.758) V46(-9.773,2.558) V48(-9.773,3.358) V49(-9.773,4.158) V51(-9.773,4.958) V53(-9.773,5.758) V55(-9.773,6.558) V56(-9.773,7.358) V58(-9.773,8.158) V60(-9.773,8.959) V62(-9.773,9.759) V64(-9.658,10.732) V67(-9.658,12.449) V71(-9.658,14.166) W9(-9.163,-14.166) W13(-9.163,-12.449) W16(-9.163,-10.732) W20(-9.163,-9.014) W24(-9.163,-7.297) W28(-9.163,-5.58) W66(-9.163,11.59) W69(-9.163,13.307) W72(-9.163,15.024) Y7(-8.668,-15.024) Y11(-8.668,-13.307) Y30(-8.898,-4.506) Y32(-8.973,-3.778) Y33(-8.973,-3.043) Y35(-8.973,-2.243) Y37(-8.973,-1.443) Y39(-8.973,-0.643) Y40(-8.973,0.157) Y42(-8.973,0.958) Y53(-8.973,5.758) Y55(-8.973,6.558) Y56(-8.973,7.358) Y58(-8.973,8.158) Y60(-8.973,8.959) Y62(-8.973,9.759) Y64(-8.668,10.732) Y67(-8.668,12.449) Y71(-8.668,14.166)
  round 0.356 smd: A6(-18.064,-15.219) A73(-18.064,15.219) AA2(-8.416,-17.327) AA4(-8.416,-16.337) AA75(-8.416,16.337) AA77(-8.416,17.327) AB3(-7.921,-16.832) AB5(-7.921,-15.842) AB74(-7.921,15.842) AB76(-7.921,16.832) AC2(-7.426,-17.327) AC4(-7.426,-16.337) AC75(-7.426,16.337) AC77(-7.426,17.327) AD3(-6.931,-16.832) AD5(-6.931,-15.842) AD74(-6.931,15.842) AD76(-6.931,16.832) AE2(-6.436,-17.327) AE4(-6.436,-16.337) AE75(-6.436,16.337) AE77(-6.436,17.327) AF3(-5.941,-16.832) AF5(-5.941,-15.842) AF74(-5.941,15.842) AF76(-5.941,16.832) AG2(-5.446,-17.327) AG4(-5.446,-16.337) AG75(-5.446,16.337) AG77(-5.446,17.327) AH3(-4.95,-16.832) AH5(-4.95,-15.842) AH74(-4.95,15.842) AH76(-4.95,16.832) AK2(-4.455,-17.327) AK4(-4.455,-16.337) AK75(-4.455,16.337) AK77(-4.455,17.327) AL3(-3.96,-16.832) AL5(-3.96,-15.842) AL74(-3.96,15.842) AL76(-3.96,16.832) AM2(-3.465,-17.327) AM4(-3.465,-16.337) AM75(-3.465,16.337) AM77(-3.465,17.327) AN3(-2.97,-16.832) AN5(-2.97,-15.842) AN74(-2.97,15.842) AN76(-2.97,16.832) AP2(-2.475,-17.327) AP4(-2.475,-16.337) AP75(-2.475,16.337) AP77(-2.475,17.327) AR3(-1.98,-16.832) AR5(-1.98,-15.842) AR74(-1.98,15.842) AR76(-1.98,16.832) AT2(-1.485,-17.327) AT4(-1.485,-16.337) AT75(-1.485,16.337) AT77(-1.485,17.327) AU3(-0.99,-16.832) AU5(-0.99,-15.842) AU74(-0.99,15.842) AU76(-0.99,16.832) AV2(-0.495,-17.327) AV4(-0.495,-16.337) AV75(-0.495,16.337) AV77(-0.495,17.327) AW3(0,-16.832) AW5(0,-15.842) AW74(0,15.842) AW76(0,16.832) AY2(0.495,-17.327) AY4(0.495,-16.337) AY75(0.495,16.337) AY77(0.495,17.327) B3(-17.353,-16.642) B10(-17.327,-13.366) B13(-17.327,-12.376) B15(-17.327,-11.386) B17(-17.327,-10.396) B19(-17.327,-9.406) B21(-17.327,-8.416) B24(-17.327,-7.426) B26(-17.327,-6.436) B28(-17.327,-5.446) B30(-17.327,-4.455) B32(-17.327,-3.465) B35(-17.327,-2.475) B37(-17.327,-1.485) B39(-17.327,-0.495) B41(-17.327,0.495) B43(-17.327,1.485) B46(-17.327,2.475) B48(-17.327,3.465) B50(-17.327,4.455) B52(-17.327,5.446) B54(-17.327,6.436) B57(-17.327,7.426) B59(-17.327,8.416) B61(-17.327,9.406) B63(-17.327,10.396) B65(-17.327,11.386) B67(-17.327,12.376) B69(-17.327,13.366) B76(-17.353,16.642) BA3(0.99,-16.832) BA5(0.99,-15.842) BA74(0.99,15.842) BA76(0.99,16.832) BB2(1.485,-17.327) BB4(1.485,-16.337) BB75(1.485,16.337) BB77(1.485,17.327) BD3(1.98,-16.832) BD5(1.98,-15.842) BD74(1.98,15.842) BD76(1.98,16.832) BE2(2.475,-17.327) BE4(2.475,-16.337) BE75(2.475,16.337) BE77(2.475,17.327) BF3(2.97,-16.832) BF5(2.97,-15.842) BF74(2.97,15.842) BF76(2.97,16.832) BG2(3.465,-17.327) BG4(3.465,-16.337) BG75(3.465,16.337) BG77(3.465,17.327) BH3(3.96,-16.832) BH5(3.96,-15.842) BH74(3.96,15.842) BH76(3.96,16.832) BJ2(4.455,-17.327) BJ4(4.455,-16.337) BJ75(4.455,16.337) BJ77(4.455,17.327) BK3(4.95,-16.832) BK5(4.95,-15.842) BK74(4.95,15.842) BK76(4.95,16.832) BL2(5.446,-17.327) BL4(5.446,-16.337) BL75(5.446,16.337) BL77(5.446,17.327) BM3(5.941,-16.832) BM5(5.941,-15.842) BM74(5.941,15.842) BM76(5.941,16.832) BN2(6.436,-17.327) BN4(6.436,-16.337) BN75(6.436,16.337) BN77(6.436,17.327) BP3(6.931,-16.832) BP5(6.931,-15.842) BP74(6.931,15.842) BP76(6.931,16.832) BR2(7.426,-17.327) BR4(7.426,-16.337) BR75(7.426,16.337) BR77(7.426,17.327) BT3(7.921,-16.832) BT5(7.921,-15.842) BT74(7.921,15.842) BT76(7.921,16.832) BU2(8.416,-17.327) BU4(8.416,-16.337) BU75(8.416,16.337) BU77(8.416,17.327) BW3(8.911,-16.832) BW5(8.911,-15.842) BW74(8.911,15.842) BW76(8.911,16.832) BY2(9.406,-17.327) BY4(9.406,-16.337) BY75(9.406,16.337) BY77(9.406,17.327) C2(-16.642,-17.353) C9(-16.832,-13.861) C12(-16.832,-12.871) C14(-16.832,-11.881) C16(-16.832,-10.891) C18(-16.832,-9.901) C20(-16.832,-8.911) C23(-16.832,-7.921) C25(-16.832,-6.931) C27(-16.832,-5.941) C29(-16.832,-4.95) C31(-16.832,-3.96) C34(-16.832,-2.97) C36(-16.832,-1.98) C38(-16.832,-0.99) C40(-16.832,0) C42(-16.832,0.99) C44(-16.832,1.98) C47(-16.832,2.97) C49(-16.832,3.96) C51(-16.832,4.95) C53(-16.832,5.941) C55(-16.832,6.931) C58(-16.832,7.921) C60(-16.832,8.911) C62(-16.832,9.901) C64(-16.832,10.891) C66(-16.832,11.881) C68(-16.832,12.871) C70(-16.832,13.861) C77(-16.642,17.353) CA3(9.901,-16.832) CA5(9.901,-15.842) CA74(9.901,15.842) CA76(9.901,16.832) CB2(10.396,-17.327) CB4(10.396,-16.337) CB75(10.396,16.337) CB77(10.396,17.327) CC3(10.891,-16.832) CC5(10.891,-15.842) CC74(10.891,15.842) CC76(10.891,16.832) CD2(11.386,-17.327) CD4(11.386,-16.337) CD75(11.386,16.337) CD77(11.386,17.327) CE3(11.881,-16.832) CE5(11.881,-15.842) CE74(11.881,15.842) CE76(11.881,16.832) CF2(12.376,-17.327) CF4(12.376,-16.337) CF75(12.376,16.337) CF77(12.376,17.327) CG3(12.871,-16.832) CG5(12.871,-15.842) CG74(12.871,15.842) CG76(12.871,16.832) CH2(13.366,-17.327) CH4(13.366,-16.337) CH75(13.366,16.337) CH77(13.366,17.327) CJ3(13.861,-16.832) CJ5(13.861,-15.842) CJ74(13.861,15.842) CJ76(13.861,16.832) CK4(14.356,-16.337) CK75(14.356,16.337) CM1(15.219,-18.064) CM78(15.219,18.064) CP9(15.842,-13.861) CP12(15.842,-12.871) CP14(15.842,-11.881) CP16(15.842,-10.891) CP18(15.842,-9.901) CP20(15.842,-8.911) CP23(15.842,-7.921) CP25(15.842,-6.931) CP27(15.842,-5.941) CP29(15.842,-4.95) CP31(15.842,-3.96) CP34(15.842,-2.97) CP36(15.842,-1.98) CP38(15.842,-0.99) CP40(15.842,0) CP42(15.842,0.99) CP44(15.842,1.98) CP47(15.842,2.97) CP49(15.842,3.96) CP51(15.842,4.95) CP53(15.842,5.941) CP55(15.842,6.931) CP58(15.842,7.921) CP60(15.842,8.911) CP62(15.842,9.901) CP64(15.842,10.891) CP66(15.842,11.881) CP68(15.842,12.871) CP70(15.842,13.861) CR2(16.642,-17.353) CR8(16.337,-14.356) CR10(16.337,-13.366) CR13(16.337,-12.376) CR15(16.337,-11.386) CR17(16.337,-10.396) CR19(16.337,-9.406) CR21(16.337,-8.416) CR24(16.337,-7.426) CR26(16.337,-6.436) CR28(16.337,-5.446) CR30(16.337,-4.455) CR32(16.337,-3.465) CR35(16.337,-2.475) CR37(16.337,-1.485) CR39(16.337,-0.495) CR41(16.337,0.495) CR43(16.337,1.485) CR46(16.337,2.475) CR48(16.337,3.465) CR50(16.337,4.455) CR52(16.337,5.446) CR54(16.337,6.436) CR57(16.337,7.426) CR59(16.337,8.416) CR61(16.337,9.406) CR63(16.337,10.396) CR65(16.337,11.386) CR67(16.337,12.376) CR69(16.337,13.366) CR71(16.337,14.356) CR77(16.642,17.353) CT9(16.832,-13.861) CT12(16.832,-12.871) CT14(16.832,-11.881) CT16(16.832,-10.891) CT18(16.832,-9.901) CT20(16.832,-8.911) CT23(16.832,-7.921) CT25(16.832,-6.931) CT27(16.832,-5.941) CT29(16.832,-4.95) CT31(16.832,-3.96) CT34(16.832,-2.97) CT36(16.832,-1.98) CT38(16.832,-0.99) CT40(16.832,0) CT42(16.832,0.99) CT44(16.832,1.98) CT47(16.832,2.97) CT49(16.832,3.96) CT51(16.832,4.95) CT53(16.832,5.941) CT55(16.832,6.931) CT58(16.832,7.921) CT60(16.832,8.911) CT62(16.832,9.901) CT64(16.832,10.891) CT66(16.832,11.881) CT68(16.832,12.871) CT70(16.832,13.861) CU3(17.353,-16.642) CU10(17.327,-13.366) CU13(17.327,-12.376) CU15(17.327,-11.386) CU17(17.327,-10.396) CU19(17.327,-9.406) CU21(17.327,-8.416) CU24(17.327,-7.426) CU26(17.327,-6.436) CU28(17.327,-5.446) CU30(17.327,-4.455) CU32(17.327,-3.465) CU35(17.327,-2.475) CU37(17.327,-1.485) CU39(17.327,-0.495) CU41(17.327,0.495) CU43(17.327,1.485) CU46(17.327,2.475) CU48(17.327,3.465) CU50(17.327,4.455) CU52(17.327,5.446) CU54(17.327,6.436) CU57(17.327,7.426) CU59(17.327,8.416) CU61(17.327,9.406) CU63(17.327,10.396) CU65(17.327,11.386) CU67(17.327,12.376) CU69(17.327,13.366) CU76(17.353,16.642) CV6(18.064,-15.219) CV73(18.064,15.219) D8(-16.337,-14.356) D10(-16.337,-13.366) D13(-16.337,-12.376) D15(-16.337,-11.386) D17(-16.337,-10.396) D19(-16.337,-9.406) D21(-16.337,-8.416) D24(-16.337,-7.426) D26(-16.337,-6.436) D28(-16.337,-5.446) D30(-16.337,-4.455) D32(-16.337,-3.465) D35(-16.337,-2.475) D37(-16.337,-1.485) D39(-16.337,-0.495) D41(-16.337,0.495) D43(-16.337,1.485) D46(-16.337,2.475) D48(-16.337,3.465) D50(-16.337,4.455) D52(-16.337,5.446) D54(-16.337,6.436) D57(-16.337,7.426) D59(-16.337,8.416) D61(-16.337,9.406) D63(-16.337,10.396) D65(-16.337,11.386) D67(-16.337,12.376) D69(-16.337,13.366) D71(-16.337,14.356) E9(-15.842,-13.861) E12(-15.842,-12.871) E14(-15.842,-11.881) E16(-15.842,-10.891) E18(-15.842,-9.901) E20(-15.842,-8.911) E23(-15.842,-7.921) E25(-15.842,-6.931) E27(-15.842,-5.941) E29(-15.842,-4.95) E31(-15.842,-3.96) E34(-15.842,-2.97) E36(-15.842,-1.98) E38(-15.842,-0.99) E40(-15.842,0) E42(-15.842,0.99) E44(-15.842,1.98) E47(-15.842,2.97) E49(-15.842,3.96) E51(-15.842,4.95) E53(-15.842,5.941) E55(-15.842,6.931) E58(-15.842,7.921) E60(-15.842,8.911) E62(-15.842,9.901) E64(-15.842,10.891) E66(-15.842,11.881) E68(-15.842,12.871) E70(-15.842,13.861) F1(-15.219,-18.064) F78(-15.219,18.064) H4(-14.356,-16.337) H75(-14.356,16.337) J3(-13.861,-16.832) J5(-13.861,-15.842) J74(-13.861,15.842) J76(-13.861,16.832) K2(-13.366,-17.327) K4(-13.366,-16.337) K75(-13.366,16.337) K77(-13.366,17.327) L3(-12.871,-16.832) L5(-12.871,-15.842) L74(-12.871,15.842) L76(-12.871,16.832) M2(-12.376,-17.327) M4(-12.376,-16.337) M75(-12.376,16.337) M77(-12.376,17.327) N3(-11.881,-16.832) N5(-11.881,-15.842) N74(-11.881,15.842) N76(-11.881,16.832) R2(-11.386,-17.327) R4(-11.386,-16.337) R75(-11.386,16.337) R77(-11.386,17.327) T3(-10.891,-16.832) T5(-10.891,-15.842) T74(-10.891,15.842) T76(-10.891,16.832) U2(-10.396,-17.327) U4(-10.396,-16.337) U75(-10.396,16.337) U77(-10.396,17.327) V3(-9.901,-16.832) V5(-9.901,-15.842) V74(-9.901,15.842) V76(-9.901,16.832) W2(-9.406,-17.327) W4(-9.406,-16.337) W75(-9.406,16.337) W77(-9.406,17.327) Y3(-8.911,-16.832) Y5(-8.911,-15.842) Y74(-8.911,15.842) Y76(-8.911,16.832)
  oval 0.343x0.254 smd: A9(-18.064,-13.861) A12(-18.064,-12.871) A14(-18.064,-11.881) A16(-18.064,-10.891) A18(-18.064,-9.901) A20(-18.064,-8.911) A23(-18.064,-7.921) A25(-18.064,-6.931) A27(-18.064,-5.941) A29(-18.064,-4.95) A31(-18.064,-3.96) A34(-18.064,-2.97) A36(-18.064,-1.98) A38(-18.064,-0.99) A40(-18.064,0) A42(-18.064,0.99) A44(-18.064,1.98) A47(-18.064,2.97) A49(-18.064,3.96) A51(-18.064,4.95) A53(-18.064,5.941) A55(-18.064,6.931) A58(-18.064,7.921) A60(-18.064,8.911) A62(-18.064,9.901) A64(-18.064,10.891) A66(-18.064,11.881) A68(-18.064,12.871) A70(-18.064,13.861) CV9(18.064,-13.861) CV12(18.064,-12.871) CV14(18.064,-11.881) CV16(18.064,-10.891) CV18(18.064,-9.901) CV20(18.064,-8.911) CV23(18.064,-7.921) CV25(18.064,-6.931) CV27(18.064,-5.941) CV29(18.064,-4.95) CV31(18.064,-3.96) CV34(18.064,-2.97) CV36(18.064,-1.98) CV38(18.064,-0.99) CV40(18.064,0) CV42(18.064,0.99) CV44(18.064,1.98) CV47(18.064,2.97) CV49(18.064,3.961) CV51(18.064,4.951) CV53(18.064,5.941) CV55(18.064,6.931) CV58(18.064,7.921) CV60(18.064,8.911) CV62(18.064,9.901) CV64(18.064,10.891) CV66(18.064,11.881) CV68(18.064,12.871) CV70(18.064,13.862)
  round 0.584 smd: A77(-18.064,17.353) B78(-17.353,18.064) CU1(17.353,-18.064) CU78(17.353,18.064) CV2(18.064,-17.353) CV77(18.064,17.353)
  oval 0.254x0.343 smd: AB1(-7.921,-18.064) AB78(-7.921,18.064) AD1(-6.931,-18.064) AD78(-6.931,18.064) AF1(-5.941,-18.064) AF78(-5.941,18.064) AH1(-4.95,-18.064) AH78(-4.95,18.064) AL1(-3.96,-18.064) AL78(-3.96,18.064) AN1(-2.97,-18.064) AN78(-2.97,18.064) AR1(-1.98,-18.064) AR78(-1.98,18.064) AU1(-0.99,-18.064) AU78(-0.99,18.064) AW1(0,-18.064) AW78(0,18.064) BA1(0.99,-18.064) BA78(0.99,18.064) BD1(1.98,-18.064) BD78(1.98,18.064) BF1(2.97,-18.064) BF78(2.97,18.064) BH1(3.96,-18.064) BH78(3.96,18.064) BK1(4.95,-18.064) BK78(4.95,18.064) BM1(5.941,-18.064) BM78(5.941,18.064) BP1(6.931,-18.064) BP78(6.931,18.064) BT1(7.921,-18.064) BT78(7.921,18.064) BW1(8.911,-18.064) BW78(8.911,18.064) CA1(9.901,-18.064) CA78(9.901,18.064) CC1(10.891,-18.064) CC78(10.891,18.064) CE1(11.881,-18.064) CE78(11.881,18.064) CG1(12.871,-18.064) CG78(12.871,18.064) CJ1(13.861,-18.064) CJ78(13.861,18.064) J1(-13.861,-18.064) J78(-13.861,18.064) L1(-12.871,-18.064) L78(-12.871,18.064) N1(-11.881,-18.064) N78(-11.881,18.064) T1(-10.891,-18.064) T78(-10.891,18.064) V1(-9.901,-18.064) V78(-9.901,18.064) Y1(-8.911,-18.064) Y78(-8.911,18.064)
  round 0.305 smd: B5(-17.353,-15.931) B8(-17.327,-14.54) B71(-17.327,14.54) B74(-17.353,15.931) C3(-16.642,-16.642) C7(-16.832,-15.136) C73(-16.832,15.136) C76(-16.642,16.642) CL2(14.54,-17.327) CL5(14.851,-15.842) CL74(14.851,15.842) CL77(14.54,17.327) CM3(15.136,-16.832) CM76(15.136,16.832) CN4(15.73,-16.337) CN5(15.641,-15.641) CN74(15.641,15.641) CN75(15.73,16.337) CP2(15.931,-17.353) CP7(15.842,-14.851) CP72(15.842,14.851) CP77(15.931,17.353) CR3(16.642,-16.642) CR5(16.337,-15.73) CR74(16.337,15.73) CR76(16.642,16.642) CT7(16.832,-15.136) CT73(16.832,15.136) CU5(17.365,-15.841) CU8(17.327,-14.54) CU71(17.327,14.54) CU74(17.353,15.931) D5(-16.337,-15.73) D74(-16.337,15.73) E2(-15.931,-17.353) E4(-15.73,-16.337) E5(-15.641,-15.641) E7(-15.842,-14.851) E72(-15.842,14.851) E74(-15.641,15.641) E75(-15.73,16.337) E77(-15.931,17.353) F3(-15.136,-16.832) F76(-15.136,16.832) G5(-14.851,-15.842) G74(-14.851,15.842) H2(-14.54,-17.327) H77(-14.54,17.327)
